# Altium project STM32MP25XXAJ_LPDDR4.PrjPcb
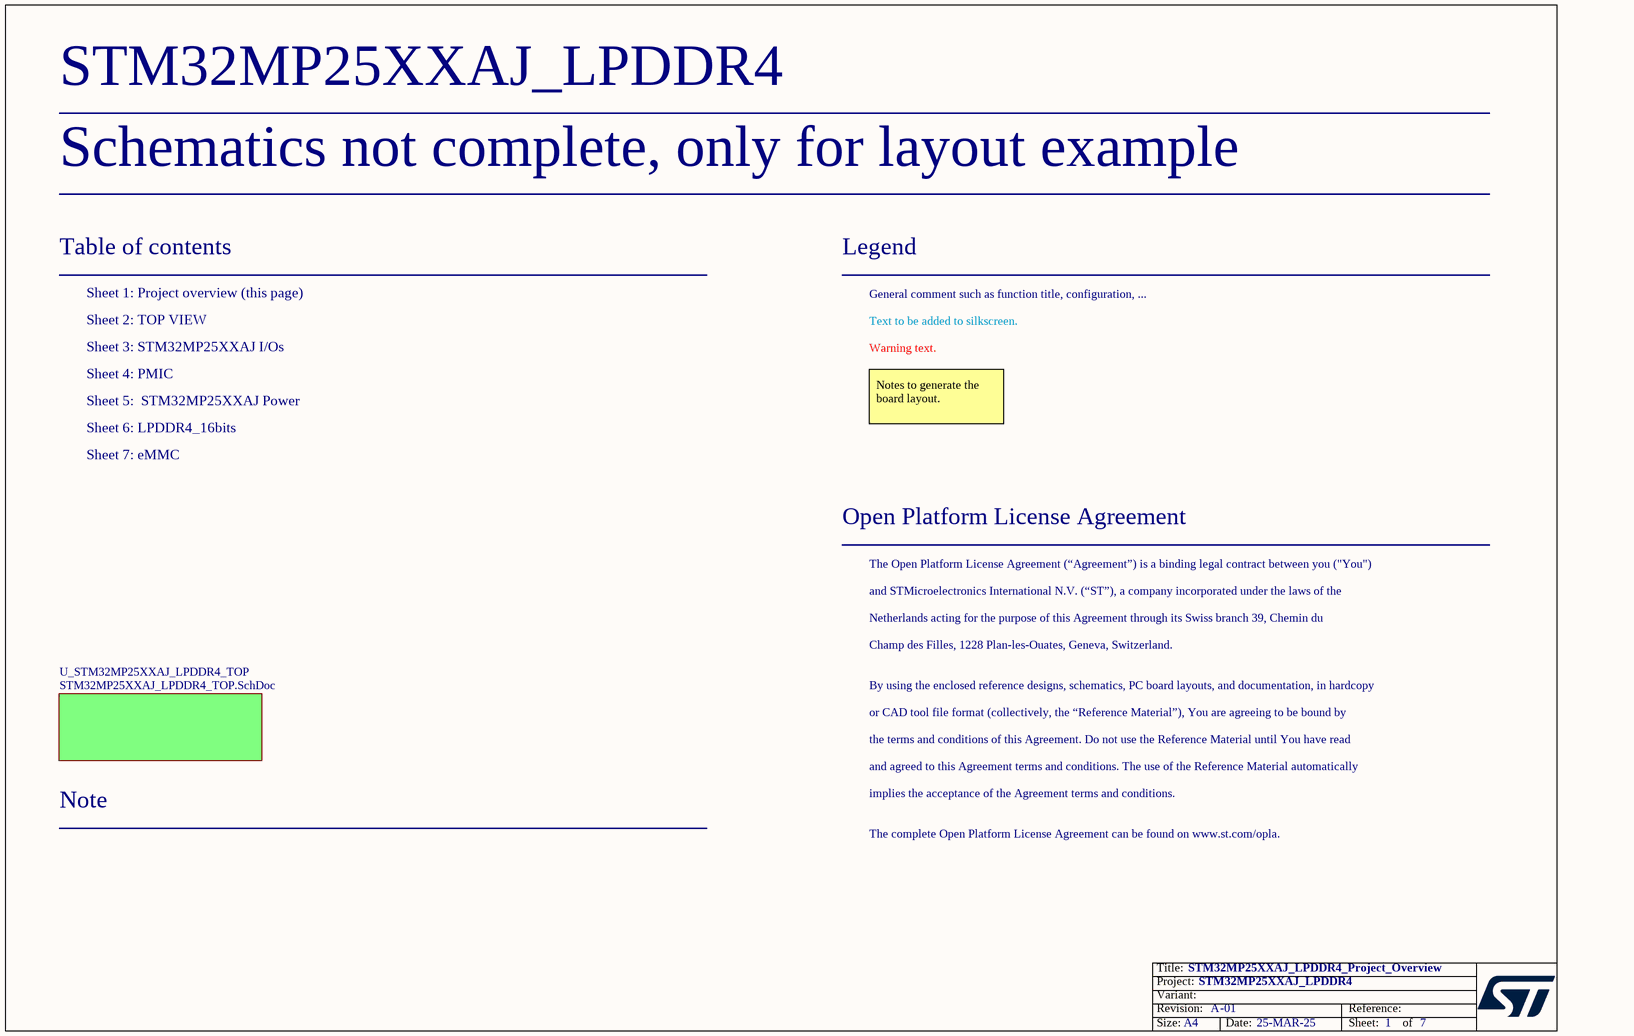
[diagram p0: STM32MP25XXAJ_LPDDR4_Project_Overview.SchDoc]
Board_Assembly_Revision: 01; Board_Document_Date: 25-MAR-25; Board_Name: STM32MP25XXAJ_LPDDR4; Board_PCB_Revision: A
7 sheets, 188 parts. Net scope: flat (ports and power ports of the same name join across sheets).
Board file: STM32MP25XXAJ_LPDDR4.PcbDoc
Sheets:
  STM32MP25XXAJ_LPDDR4_Project_Overview.SchDoc
    U_STM32MP25XXAJ_LPDDR4_TOP = STM32MP25XXAJ_LPDDR4_TOP.SchDoc
      U_STM32MP25XXAJ I_Os = STM32MP25XXAJ I_Os.SchDoc
      U_PMIC = PMIC.SchDoc
      U_STM32MP25XXAJ Power = STM32MP25XXAJ Power.SchDoc
      U_eMMC = eMMC.SchDoc
      U_LPDDR4_16bits = LPDDR4_16bits.SchDoc

## Sheet STM32MP25XXAJ_LPDDR4_Project_Overview.SchDoc: STM32MP25XXAJ_LPDDR4_Project_Overview
size A4; Date: Not used; ApprovedBy: Not used; CheckedBy: Not used; Author: Not used; CompanyName: STMicroelectronics; DrawnBy: Not used; Engineer: Not used; Organization: Not used; Address1: Not used; Address2: Not used; Address3: Not used; Address4: Not used; DocumentNumber: 1; Revision: Not used; SheetNumber: 1; SheetTotal: 7

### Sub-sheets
U_STM32MP25XXAJ_LPDDR4_TOP = STM32MP25XXAJ_LPDDR4_TOP.SchDoc: no entries

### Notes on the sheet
- Schematics not complete, only for layout example
- Table of contents
- Sheet 1: Project overview (this page)
- Legend
- General comment such as function title, configuration, ...
- Sheet 2: TOP VIEW
- Sheet 3: STM32MP25XXAJ I/Os
- Sheet 4: PMIC
- Text to be added to silkscreen.
- Warning text.
- Sheet 5:  STM32MP25XXAJ Power
- Sheet 6: LPDDR4_16bits
- Notes to generate the board layout.
- Sheet 7: eMMC
- Open Platform License Agreement
- The Open Platform License Agreement (“Agreement”) is a binding legal contract between you ("You")
- and STMicroelectronics International N.V. (“ST”), a company incorporated under the laws of the
- Netherlands acting for the purpose of this Agreement through its Swiss branch 39, Chemin du
- Champ des Filles, 1228 Plan-les-Ouates, Geneva, Switzerland.
- By using the enclosed reference designs, schematics, PC board layouts, and documentation, in hardcopy
- or CAD tool file format (collectively, the “Reference Material”), You are agreeing to be bound by
- the terms and conditions of this Agreement. Do not use the Reference Material until You have read
- and agreed to this Agreement terms and conditions. The use of the Reference Material automatically
- Note
- implies the acceptance of the Agreement terms and conditions.
- The complete Open Platform License Agreement can be found on www.st.com/opla.

## Sheet STM32MP25XXAJ_LPDDR4_TOP.SchDoc: TOP
size A4; Date: Not used; ApprovedBy: Not used; CheckedBy: Not used; Author: Not used; CompanyName: STMicroelectronics; DrawnBy: Not used; Engineer: Not used; Organization: Not used; Address1: Not used; Address2: Not used; Address3: Not used; Address4: Not used; DocumentNumber: 2; Revision: Not used; SheetNumber: 2; SheetTotal: 7
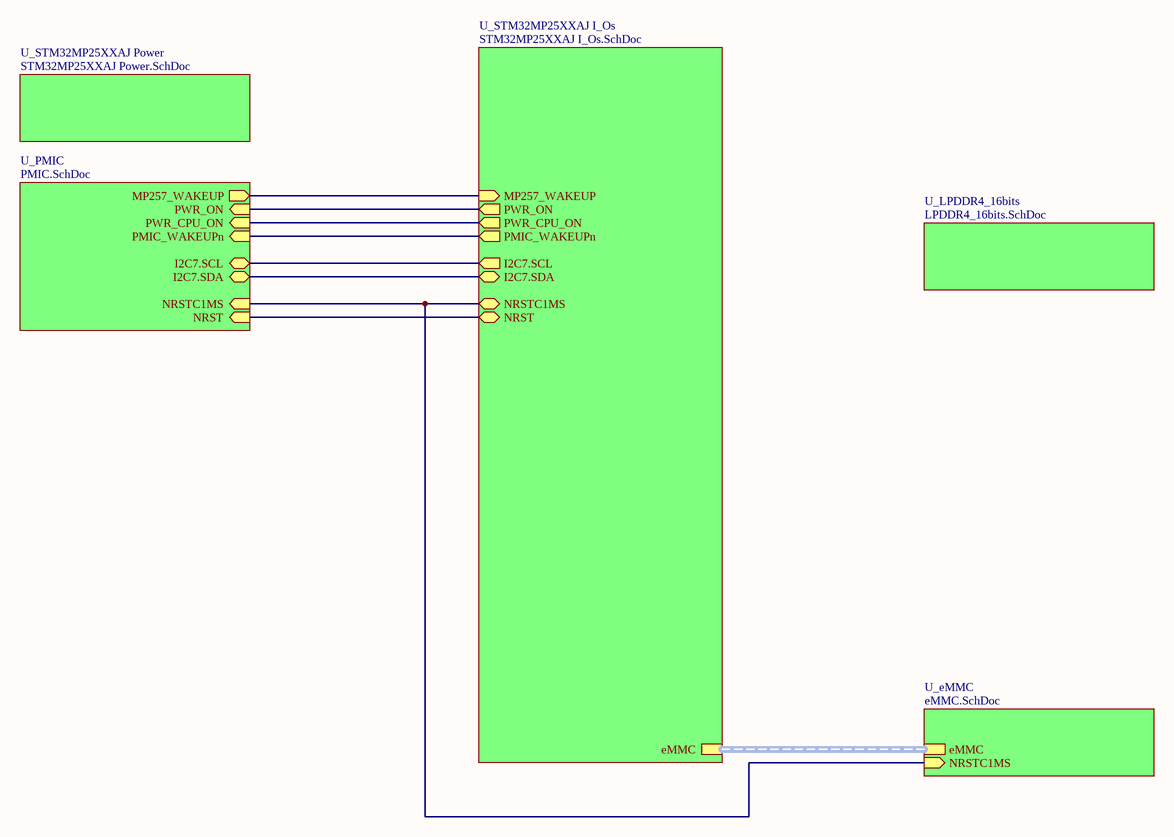
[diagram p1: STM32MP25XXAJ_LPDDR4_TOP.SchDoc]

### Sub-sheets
U_eMMC = eMMC.SchDoc: eMMC (harness eMMC), NRSTC1MS (in)
U_LPDDR4_16bits = LPDDR4_16bits.SchDoc: no entries
U_PMIC = PMIC.SchDoc: PMIC_WAKEUPn (in), NRST (in), I2C7.SCL (bidir), PWR_ON (in), PWR_CPU_ON (in), NRSTC1MS (in), I2C7.SDA (bidir), MP257_WAKEUP (out)
U_STM32MP25XXAJ I_Os = STM32MP25XXAJ I_Os.SchDoc: NRST (bidir), PWR_ON (out), NRSTC1MS (bidir), I2C7.SDA (bidir), I2C7.SCL (out), PWR_CPU_ON (out), MP257_WAKEUP (in), PMIC_WAKEUPn (out), eMMC (harness eMMC)
U_STM32MP25XXAJ Power = STM32MP25XXAJ Power.SchDoc: no entries

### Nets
(unnamed): sheet U_STM32MP25XXAJ I_Os/NRST, sheet U_PMIC/NRST
(unnamed): sheet U_STM32MP25XXAJ I_Os/PWR_ON, sheet U_PMIC/PWR_ON  [a separate net that carries the same name]
(unnamed): sheet U_STM32MP25XXAJ I_Os/NRSTC1MS, sheet U_PMIC/NRSTC1MS, sheet U_eMMC/NRSTC1MS  [a separate net that carries the same name]
(unnamed): sheet U_STM32MP25XXAJ I_Os/I2C7.SDA, sheet U_PMIC/I2C7.SDA  [a separate net that carries the same name]
(unnamed): sheet U_STM32MP25XXAJ I_Os/I2C7.SCL, sheet U_PMIC/I2C7.SCL  [a separate net that carries the same name]
(unnamed): sheet U_STM32MP25XXAJ I_Os/PWR_CPU_ON, sheet U_PMIC/PWR_CPU_ON  [a separate net that carries the same name]
(unnamed): sheet U_STM32MP25XXAJ I_Os/MP257_WAKEUP, sheet U_PMIC/MP257_WAKEUP  [a separate net that carries the same name]
(unnamed): sheet U_STM32MP25XXAJ I_Os/PMIC_WAKEUPn, sheet U_PMIC/PMIC_WAKEUPn  [a separate net that carries the same name]

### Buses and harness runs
harness sheet U_eMMC/eMMC = sheet U_STM32MP25XXAJ I_Os/eMMC

## Sheet STM32MP25XXAJ I_Os.SchDoc: STM32MP25XXAJ  I/Os
size A3; Date: Not used; ApprovedBy: Not used; CheckedBy: Not used; Author: Not used; CompanyName: STMicroelectronics; DrawnBy: Not used; Engineer: Not used; Organization: Not used; Address1: Not used; Address2: Not used; Address3: Not used; Address4: Not used; DocumentNumber: 3; Revision: Not used; SheetNumber: 3; SheetTotal: 7
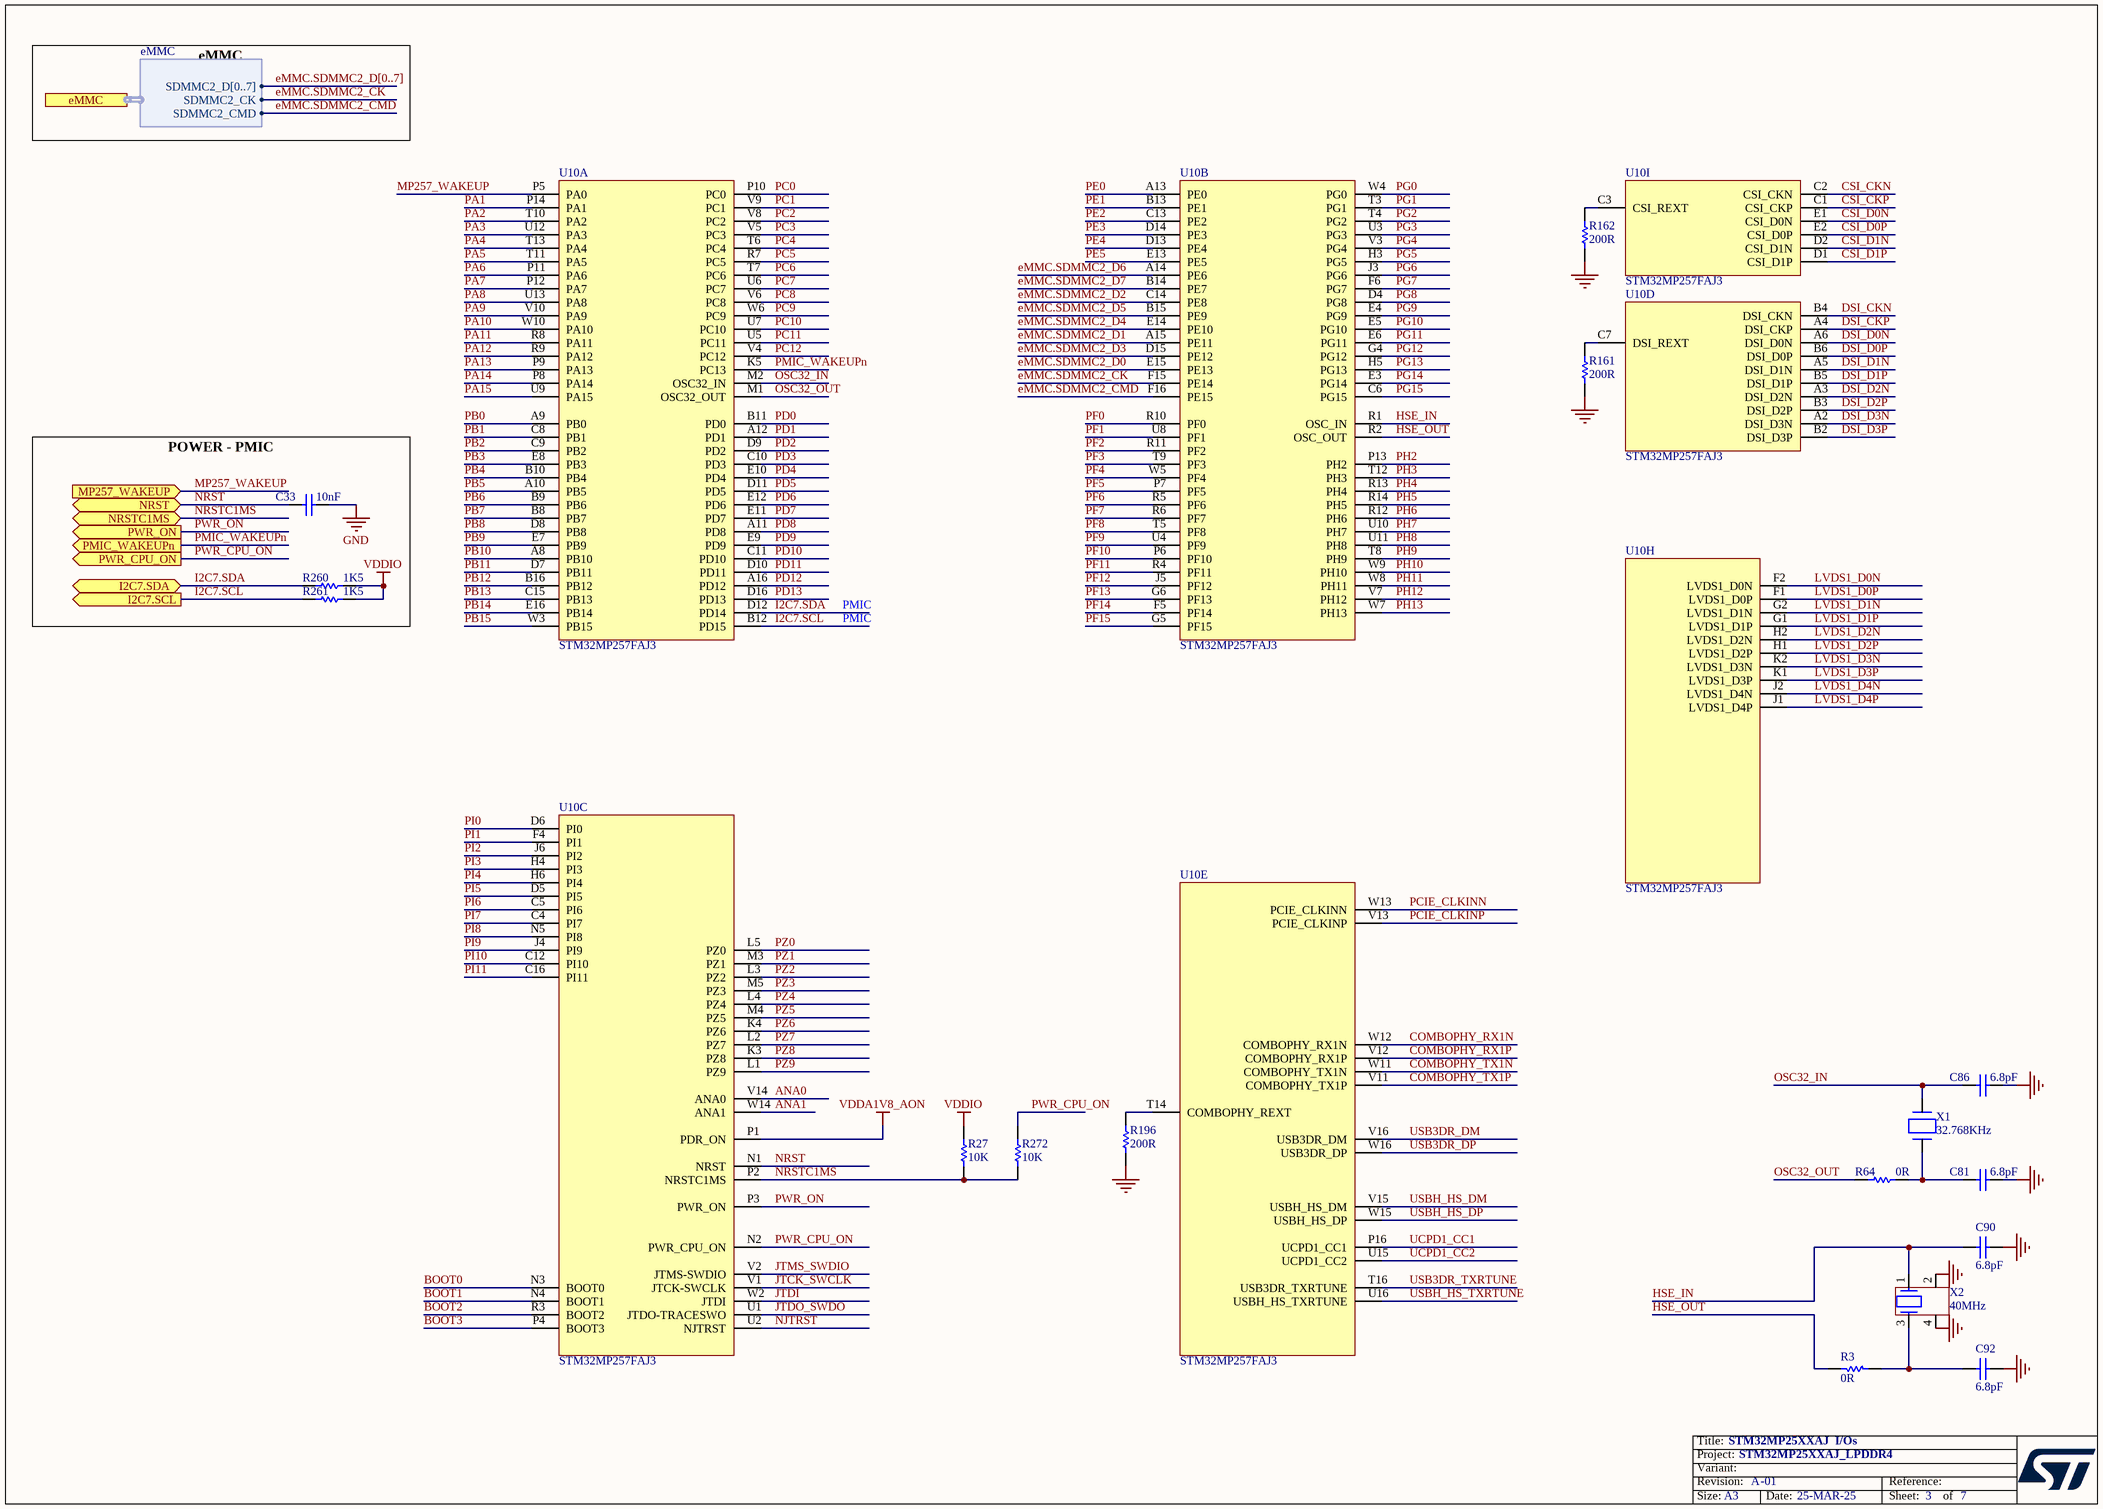
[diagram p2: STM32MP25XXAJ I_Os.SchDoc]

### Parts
C33  value 10nF  [C0402]  (hidden comment: Capacitor)
C81  value 6.8pF  [C0402]  (hidden comment: Capacitor)
C86  value 6.8pF  [C0402]  (hidden comment: Capacitor)
C90  value 6.8pF  [C0402]  (hidden comment: Capacitor)
C92  value 6.8pF  [C0402]  (hidden comment: Capacitor)
R3  value 0R  [R0402]
R27  value 10K  [R0402]  (hidden comment: Resistor)
R64  value 0R  [R0402]
R161  value 200R  [R0402]  (hidden comment: Resistor)
R162  value 200R  [R0402]  (hidden comment: Resistor)
R196  value 200R  [R0402]  (hidden comment: Resistor)
R260  value 1K5  [R0402]  (hidden comment: Resistor)
R261  value 1K5  [R0402]  (hidden comment: Resistor)
R272  value 10K  [R0402]  (hidden comment: Resistor)
U10  value STM32MP257FAJ3  [ICC_TFBGA361_16X16_P080]  (hidden comment: IC_STM32MP257FAJ3)  (parts A,B,C,D,E,H,I of 9)
X1  value 32.768KHz  [CRY_NX2012SA_2P]  (hidden comment: XTAL_2_PINS)
X2  value 40MHz  [CRY_NX1612SA_4P]  (hidden comment: XTAL_4_PINS)

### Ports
eMMC (harness eMMC), I2C7.SCL (out), I2C7.SDA (bidir), MP257_WAKEUP (in), NRST (bidir), NRSTC1MS (bidir), PMIC_WAKEUPn (out), PWR_CPU_ON (out), PWR_ON (out)

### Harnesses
eMMC: SDMMC2_CK, SDMMC2_CMD, SDMMC2_D[0..7]

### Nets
GND: C33.1 C81.2 C86.2 C90.1 C92.2 R161.2 R162.2 R196.1 X2.2 X2.4
VDDA1V8_AON: U10.P1(PDR_ON)
VDDIO: R27.2 R260.2 R261.2
ANA0: U10.V14(ANA0)
ANA1: U10.W14(ANA1)
BOOT0: U10.N3(BOOT0)
BOOT1: U10.N4(BOOT1)
BOOT2: U10.R3(BOOT2)
BOOT3: U10.P4(BOOT3)
COMBOPHY_RX1N: U10.W12(COMBOPHY_RX1N)
COMBOPHY_RX1P: U10.V12(COMBOPHY_RX1P)
COMBOPHY_TX1N: U10.W11(COMBOPHY_TX1N)
COMBOPHY_TX1P: U10.V11(COMBOPHY_TX1P)
CSI_CKN: U10.C2(CSI_CKN)
CSI_CKP: U10.C1(CSI_CKP)
CSI_D0N: U10.E1(CSI_D0N)
CSI_D0P: U10.E2(CSI_D0P)
CSI_D1N: U10.D2(CSI_D1N)
CSI_D1P: U10.D1(CSI_D1P)
DSI_CKN: U10.B4(DSI_CKN)
DSI_CKP: U10.A4(DSI_CKP)
DSI_D0N: U10.A6(DSI_D0N)
DSI_D0P: U10.B6(DSI_D0P)
DSI_D1N: U10.A5(DSI_D1N)
DSI_D1P: U10.B5(DSI_D1P)
DSI_D2N: U10.A3(DSI_D2N)
DSI_D2P: U10.B3(DSI_D2P)
DSI_D3N: U10.A2(DSI_D3N)
DSI_D3P: U10.B2(DSI_D3P)
eMMC.SDMMC2_CK: U10.F15(PE14) ; port eMMC.SDMMC2_CK
eMMC.SDMMC2_CMD: U10.F16(PE15) ; port eMMC.SDMMC2_CMD
eMMC.SDMMC2_D0: U10.E15(PE13)
eMMC.SDMMC2_D1: U10.A15(PE11)
eMMC.SDMMC2_D2: U10.C14(PE8)
eMMC.SDMMC2_D3: U10.D15(PE12)
eMMC.SDMMC2_D4: U10.E14(PE10)
eMMC.SDMMC2_D5: U10.B15(PE9)
eMMC.SDMMC2_D6: U10.A14(PE6)
eMMC.SDMMC2_D7: U10.B14(PE7)
HSE_IN: C90.2 U10.R1(OSC_IN) X2.1
HSE_OUT: R3.2 U10.R2(OSC_OUT)
I2C7.SCL: R261.1 U10.B12(PD15) ; port I2C7.SCL
I2C7.SDA: R260.1 U10.D12(PD14) ; port I2C7.SDA
JTCK_SWCLK: U10.V1(JTCK-SWCLK)
JTDI: U10.W2(JTDI)
JTDO_SWDO: U10.U1(JTDO-TRACESWO)
JTMS_SWDIO: U10.V2(JTMS-SWDIO)
LVDS1_D0N: U10.F2(LVDS1_D0N)
LVDS1_D0P: U10.F1(LVDS1_D0P)
LVDS1_D1N: U10.G2(LVDS1_D1N)
LVDS1_D1P: U10.G1(LVDS1_D1P)
LVDS1_D2N: U10.H2(LVDS1_D2N)
LVDS1_D2P: U10.H1(LVDS1_D2P)
LVDS1_D3N: U10.K2(LVDS1_D3N)
LVDS1_D3P: U10.K1(LVDS1_D3P)
LVDS1_D4N: U10.J2(LVDS1_D4N)
LVDS1_D4P: U10.J1(LVDS1_D4P)
MP257_WAKEUP: U10.P5(PA0) ; port MP257_WAKEUP
NJTRST: U10.U2(NJTRST)
NRST: C33.2 U10.N1(NRST) ; port NRST
NRSTC1MS: R27.1 R272.1 U10.P2(NRSTC1MS) ; port NRSTC1MS
OSC32_IN: C86.1 U10.M2(OSC32_IN) X1.2(X2)
OSC32_OUT: R64.1 U10.M1(OSC32_OUT)
PA1: U10.P14(PA1)
PA2: U10.T10(PA2)
PA3: U10.U12(PA3)
PA4: U10.T13(PA4)
PA5: U10.T11(PA5)
PA6: U10.P11(PA6)
PA7: U10.P12(PA7)
PA8: U10.U13(PA8)
PA9: U10.V10(PA9)
PA10: U10.W10(PA10)
PA11: U10.R8(PA11)
PA12: U10.R9(PA12)
PA13: U10.P9(PA13)
PA14: U10.P8(PA14)
PA15: U10.U9(PA15)
PB0: U10.A9(PB0)
PB1: U10.C8(PB1)
PB2: U10.C9(PB2)
PB3: U10.E8(PB3)
PB4: U10.B10(PB4)
PB5: U10.A10(PB5)
PB6: U10.B9(PB6)
PB7: U10.B8(PB7)
PB8: U10.D8(PB8)
PB9: U10.E7(PB9)
PB10: U10.A8(PB10)
PB11: U10.D7(PB11)
PB12: U10.B16(PB12)
PB13: U10.C15(PB13)
PB14: U10.E16(PB14)
PB15: U10.W3(PB15)
PC0: U10.P10(PC0)
PC1: U10.V9(PC1)
PC2: U10.V8(PC2)
PC3: U10.V5(PC3)
PC4: U10.T6(PC4)
PC5: U10.R7(PC5)
PC6: U10.T7(PC6)
PC7: U10.U6(PC7)
PC8: U10.V6(PC8)
PC9: U10.W6(PC9)
PC10: U10.U7(PC10)
PC11: U10.U5(PC11)
PC12: U10.V4(PC12)
PCIE_CLKINN: U10.W13(PCIE_CLKINN)
PCIE_CLKINP: U10.V13(PCIE_CLKINP)
PD0: U10.B11(PD0)
PD1: U10.A12(PD1)
PD2: U10.D9(PD2)
PD3: U10.C10(PD3)
PD4: U10.E10(PD4)
PD5: U10.D11(PD5)
PD6: U10.E12(PD6)
PD7: U10.E11(PD7)
PD8: U10.A11(PD8)
PD9: U10.E9(PD9)
PD10: U10.C11(PD10)
PD11: U10.D10(PD11)
PD12: U10.A16(PD12)
PD13: U10.D16(PD13)
PE0: U10.A13(PE0)
PE1: U10.B13(PE1)
PE2: U10.C13(PE2)
PE3: U10.D14(PE3)
PE4: U10.D13(PE4)
PE5: U10.E13(PE5)
PF0: U10.R10(PF0)
PF1: U10.U8(PF1)
PF2: U10.R11(PF2)
PF3: U10.T9(PF3)
PF4: U10.W5(PF4)
PF5: U10.P7(PF5)
PF6: U10.R5(PF6)
PF7: U10.R6(PF7)
PF8: U10.T5(PF8)
PF9: U10.U4(PF9)
PF10: U10.P6(PF10)
PF11: U10.R4(PF11)
PF12: U10.J5(PF12)
PF13: U10.G6(PF13)
PF14: U10.F5(PF14)
PF15: U10.G5(PF15)
PG0: U10.W4(PG0)
PG1: U10.T3(PG1)
PG2: U10.T4(PG2)
PG3: U10.U3(PG3)
PG4: U10.V3(PG4)
PG5: U10.H3(PG5)
PG6: U10.J3(PG6)
PG7: U10.F6(PG7)
PG8: U10.D4(PG8)
PG9: U10.E4(PG9)
PG10: U10.E5(PG10)
PG11: U10.E6(PG11)
PG12: U10.G4(PG12)
PG13: U10.H5(PG13)
PG14: U10.E3(PG14)
PG15: U10.C6(PG15)
PH2: U10.P13(PH2)
PH3: U10.T12(PH3)
PH4: U10.R13(PH4)
PH5: U10.R14(PH5)
PH6: U10.R12(PH6)
PH7: U10.U10(PH7)
PH8: U10.U11(PH8)
PH9: U10.T8(PH9)
PH10: U10.W9(PH10)
PH11: U10.W8(PH11)
PH12: U10.V7(PH12)
PH13: U10.W7(PH13)
PI0: U10.D6(PI0)
PI1: U10.F4(PI1)
PI2: U10.J6(PI2)
PI3: U10.H4(PI3)
PI4: U10.H6(PI4)
PI5: U10.D5(PI5)
PI6: U10.C5(PI6)
PI7: U10.C4(PI7)
PI8: U10.N5(PI8)
PI9: U10.J4(PI9)
PI10: U10.C12(PI10)
PI11: U10.C16(PI11)
PMIC_WAKEUPn: U10.K5(PC13) ; port PMIC_WAKEUPn
PWR_CPU_ON: R272.2 U10.N2(PWR_CPU_ON) ; port PWR_CPU_ON
PWR_ON: U10.P3(PWR_ON) ; port PWR_ON
PZ0: U10.L5(PZ0)
PZ1: U10.M3(PZ1)
PZ2: U10.L3(PZ2)
PZ3: U10.M5(PZ3)
PZ4: U10.L4(PZ4)
PZ5: U10.M4(PZ5)
PZ6: U10.K4(PZ6)
PZ7: U10.L2(PZ7)
PZ8: U10.K3(PZ8)
PZ9: U10.L1(PZ9)
UCPD1_CC1: U10.P16(UCPD1_CC1)
UCPD1_CC2: U10.U15(UCPD1_CC2)
USB3DR_DM: U10.V16(USB3DR_DM)
USB3DR_DP: U10.W16(USB3DR_DP)
USB3DR_TXRTUNE: U10.T16(USB3DR_TXRTUNE)
USBH_HS_DM: U10.V15(USBH_HS_DM)
USBH_HS_DP: U10.W15(USBH_HS_DP)
USBH_HS_TXRTUNE: U10.U16(USBH_HS_TXRTUNE)
NetC81_1: C81.1 R64.2 X1.1(X1)
NetC92_1: C92.1 R3.1 X2.3
NetR161_1: R161.1 U10.C7(DSI_REXT)
NetR162_1: R162.1 U10.C3(CSI_REXT)
NetR196_2: R196.2 U10.T14(COMBOPHY_REXT)

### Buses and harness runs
bus eMMC.SDMMC2_D[0..7]

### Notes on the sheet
- eMMC
- POWER - PMIC
- PMIC

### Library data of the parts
C33 = MCD-00011: Capacitor, MLCC, 10nF, 16V, X7R, 10%, 0402, T=0.5mm; Manufacturer_Part_Number: CC0402KRX7R7BB103; Manufacturer: YAGEO; Provided_By: SUBCO; Initial_Board_Reference: MB1274
C81 C86 = MCD-00674: Capacitor, MLCC, 6.8pF, 50V, NPO, +-0.25pF, 0402, T=0.5mm; Manufacturer_Part_Number: CC0402CRNPO9BN6R8; Manufacturer: YAGEO; Part_Preference: Recommended; Provided_By: SUBCO; Initial_Board_Reference: MB1319; Path: ws/MCD_ApplicationBoards/Lists/MCDPARTSdatabase; Item Type: Item; Component_Country_Of_Origin: China; ID: 3068; ShowFields: YES
C90 C92 = MCD-00674: Capacitor, MLCC, 6.8pF, 50V, NPO, +-0.25pF, 0402, T=0.5mm; Manufacturer_Part_Number: CC0402CRNPO9BN6R8; Manufacturer: YAGEO; Part_Preference: Recommended; Provided_By: SUBCO; Initial_Board_Reference: MB1319; Component_Country_Of_Origin: China; ID: 3068; ShowFields: YES
R3 R64 = MCD-00052: Resistor,0R,0402,5%,1/16W; Manufacturer_Part_Number: RC0402JR-070RL; Manufacturer: YAGEO; Part_Preference: Recommended; Provided_By: SUBCO; Initial_Board_Reference: mb1274; Order_Code_RS: 618-5804; Component_Country_Of_Origin: China; ID: 2540; ShowFields: YES
R27 R272 = MCD-00053: Resistor,10K,0402,1%,1/16W; BMS_Part_Number: 9131590; Part_Preference: Recommended; Manufacturer: YAGEO; Manufacturer_Part_Number: RC0402FR-0710KL; Component_Country_Of_Origin: China; ID: 2539; ShowFields: YES
R161 R162 = MCD-00417: Resistor,200R,0402,1%,1/16W; Manufacturer_Part_Number: RC0402FR-07200RL; Manufacturer: YAGEO; Part_Preference: Recommended; ECCN_US: EAR99; ECCN_EU: NEC; Provided_By: SUBCO
R196 = MCD-00417: Resistor,200R,0402,1%,1/16W; Part_Preference: Recommended; Manufacturer: YAGEO; Manufacturer_Part_Number: RC0402FR-07200RL
R260 R261 = MCD-00068: Resistor,1K5,0402,1%,1/16W; Part_Preference: Recommended; Manufacturer: YAGEO; Manufacturer_Part_Number: RC0402FR-071K5L; Component_Country_Of_Origin: China; ID: 2524; ShowFields: YES
U10 = MCD-04441: MPU, Dual Core ARM cortex-A35 64-bit + M33 32-bit,  808KB SRAM, With Crypto; Part_Type: IC; Part_Preference: Recommended; Manufacturer: STMICROELECTRONICS; ShowFields: YES; ID: 6557
X1 = MCD-01479: Crystal, 32.768kHz, 6pF, +/-20ppm, 80K, 2.05x1.2mm; BMS_Part_Number: 9157049; Part_Type: Crystal_Osc; Part_Preference: Recommended; Manufacturer: NDK; Manufacturer_Part_Number: NX2012SA-32.768KHZ-EXS00A-MU00527; Component_Country_Of_Origin: Unknown; ShowFields: YES; ID: 3579
X2 = MCD-02344: Crystal, 40MHz, 6pF, +/-20ppm, 80R, 1.6x1.2mm; Part_Type: Crystal_Osc; Part_Preference: Recommended; Manufacturer: NDK; Manufacturer_Part_Number: NX1612SA-40MHZ-EXS00A-CS13836; Component_Country_Of_Origin: Unknown; ShowFields: YES; ID: 4450

## Sheet PMIC.SchDoc: PMIC
size A3; Date: Not used; ApprovedBy: Not used; CheckedBy: Not used; Author: Not used; CompanyName: STMicroelectronics; DrawnBy: Not used; Engineer: Not used; Organization: Not used; Address1: Not used; Address2: Not used; Address3: Not used; Address4: Not used; DocumentNumber: 4; Revision: Not used; SheetNumber: 4; SheetTotal: 7
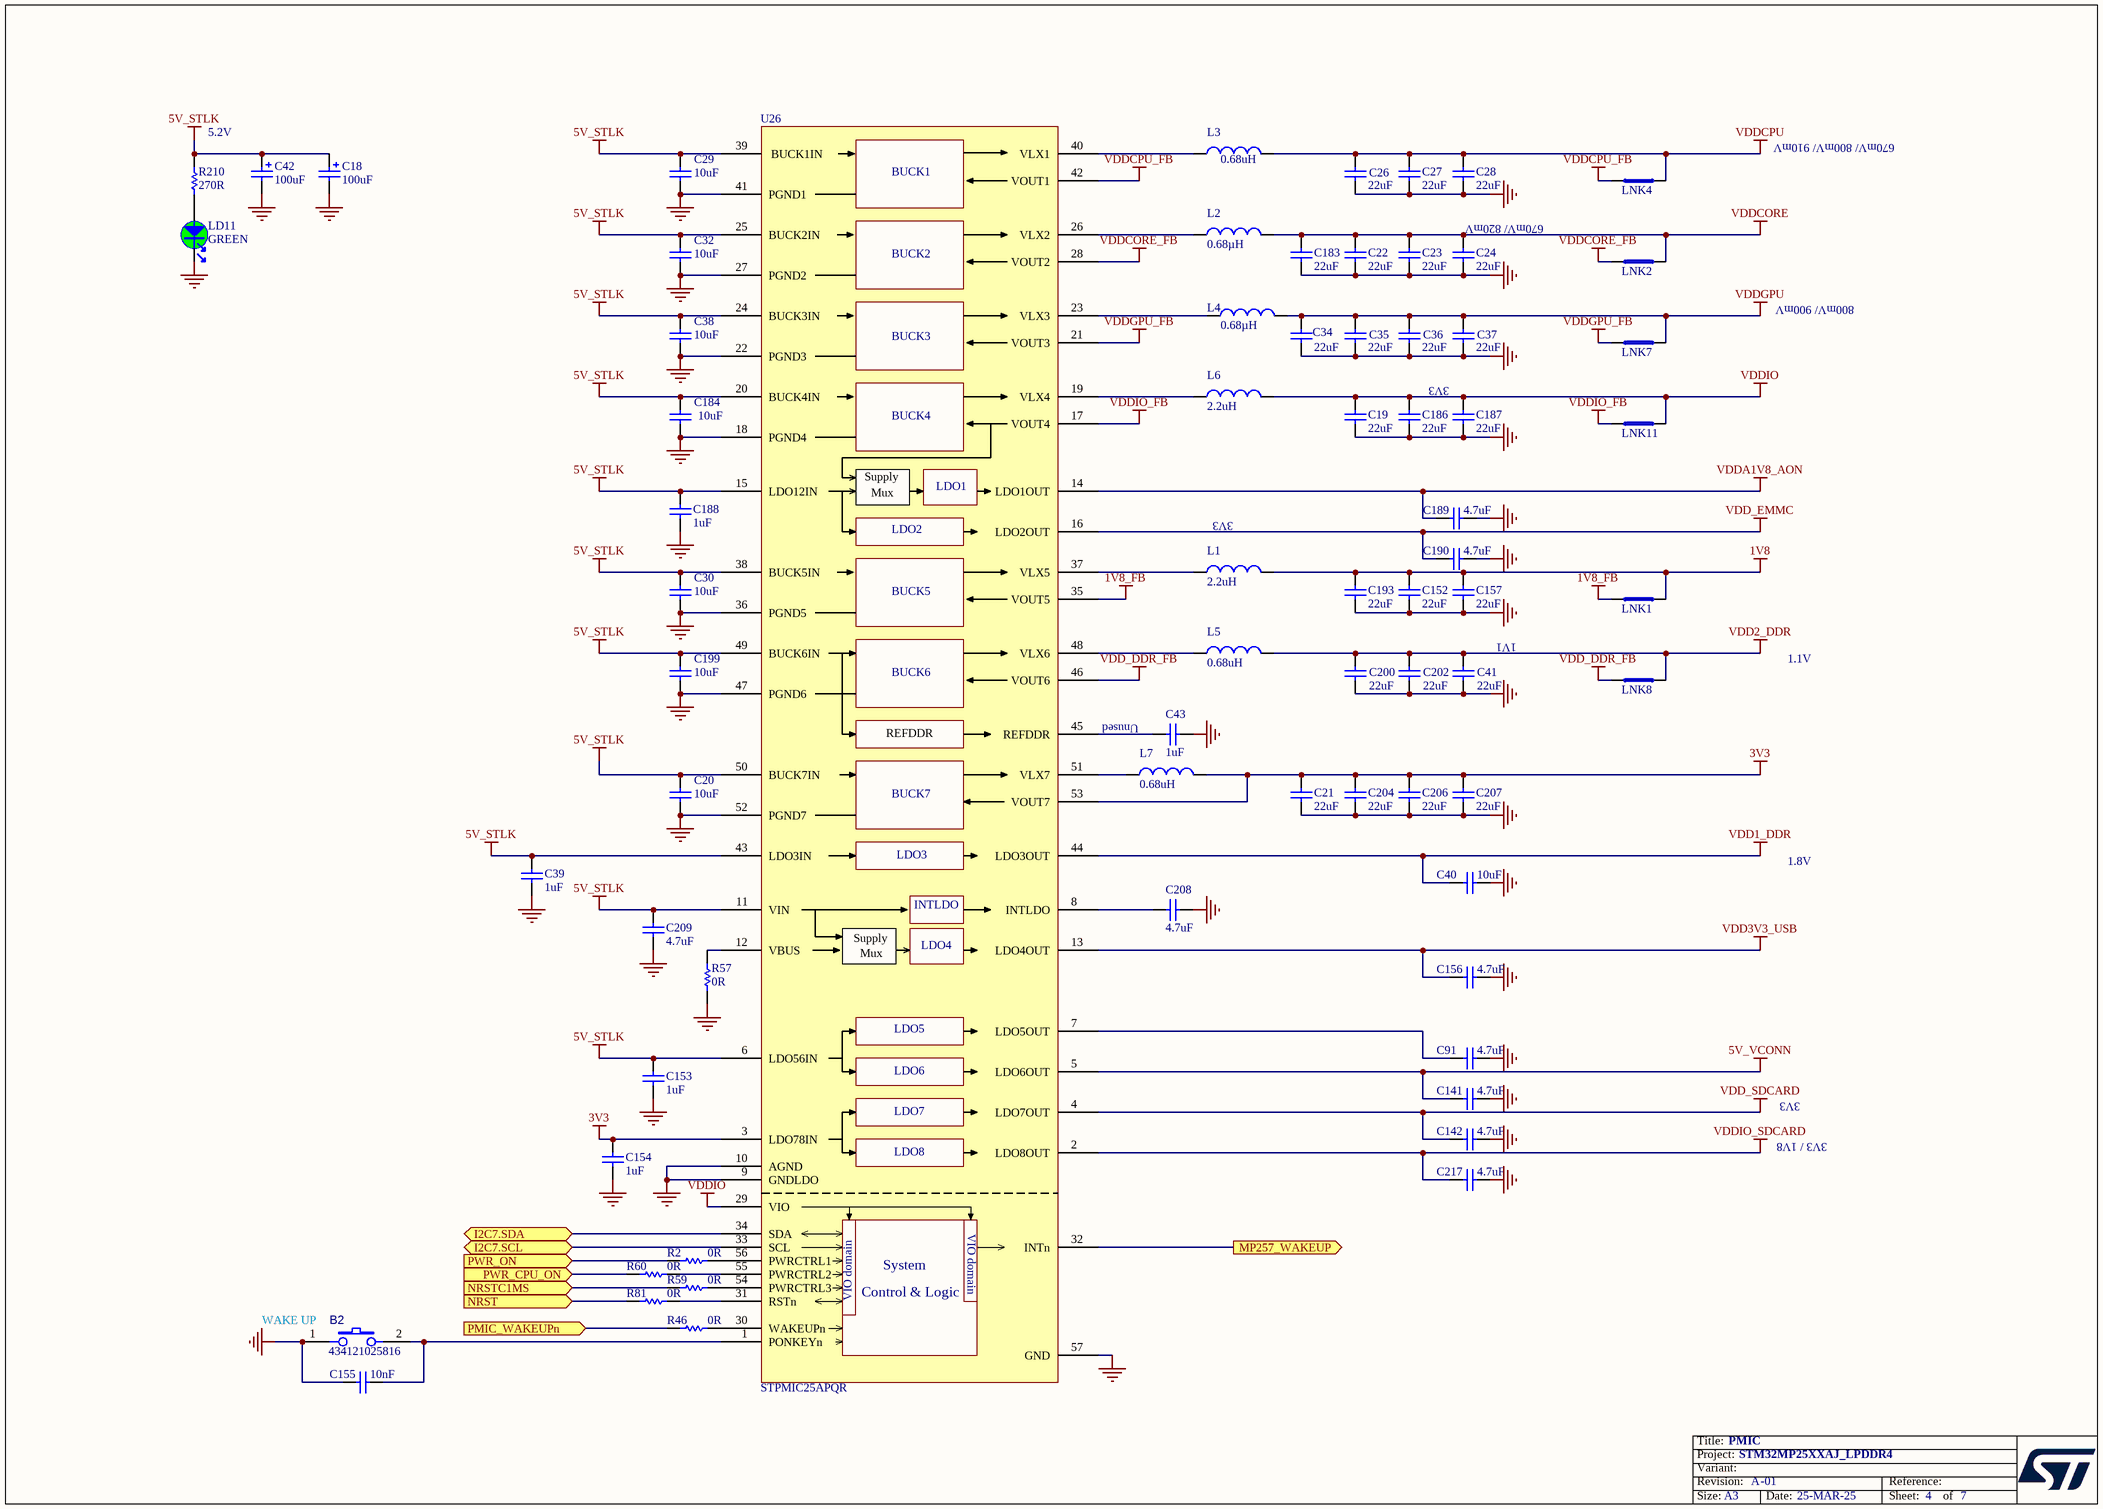
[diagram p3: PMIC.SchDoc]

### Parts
B2  value 434121025816  [SWI_WE_434121025816]  (hidden comment: SW_PUSH_SMD_2P)
C18  value 100uF  [CPOL_TCJ-B_1210_H210]  (hidden comment: Cap_POL_TANA)
C19  value 22uF  [C0805]  (hidden comment: Capacitor)
C20  value 10uF  [C0603]  (hidden comment: Capacitor)
C21  value 22uF  [C0805]  (hidden comment: Capacitor)
C22  value 22uF  [C0603]  (hidden comment: Capacitor)
C23  value 22uF  [C0603]  (hidden comment: Capacitor)
C24  value 22uF  [C0603]  (hidden comment: Capacitor)
C26  value 22uF  [C0603]  (hidden comment: Capacitor)
C27  value 22uF  [C0603]  (hidden comment: Capacitor)
C28  value 22uF  [C0603]  (hidden comment: Capacitor)
C29  value 10uF  [C0603]  (hidden comment: Capacitor)
C30  value 10uF  [C0603]  (hidden comment: Capacitor)
C32  value 10uF  [C0603]  (hidden comment: Capacitor)
C34  value 22uF  [C0603]  (hidden comment: Capacitor)
C35  value 22uF  [C0603]  (hidden comment: Capacitor)
C36  value 22uF  [C0603]  (hidden comment: Capacitor)
C37  value 22uF  [C0603]  (hidden comment: Capacitor)
C38  value 10uF  [C0603]  (hidden comment: Capacitor)
C39  value 1uF  [C0402]  (hidden comment: Capacitor)
C40  value 10uF  [C0402]  (hidden comment: Capacitor)
C41  value 22uF  [C0603]  (hidden comment: Capacitor)
C42  value 100uF  [CPOL_TCJ-B_1210_H210]  (hidden comment: Cap_POL_TANA)
C43  value 1uF  [C0402]  (hidden comment: Capacitor)
C91  value 4.7uF  [C0402]  (hidden comment: Capacitor)
C141  value 4.7uF  [C0402]  (hidden comment: Capacitor)
C142  value 4.7uF  [C0402]  (hidden comment: Capacitor)
C152  value 22uF  [C0805]  (hidden comment: Capacitor)
C153  value 1uF  [C0402]  (hidden comment: Capacitor)
C154  value 1uF  [C0402]  (hidden comment: Capacitor)
C155  value 10nF  [C0402]  (hidden comment: Capacitor)
C156  value 4.7uF  [C0402]  (hidden comment: Capacitor)
C157  value 22uF  [C0805]  (hidden comment: Capacitor)
C183  value 22uF  [C0603]  (hidden comment: Capacitor)
C184  value 10uF  [C0603]  (hidden comment: Capacitor)
C186  value 22uF  [C0805]  (hidden comment: Capacitor)
C187  value 22uF  [C0805]  (hidden comment: Capacitor)
C188  value 1uF  [C0402]  (hidden comment: Capacitor)
C189  value 4.7uF  [C0402]  (hidden comment: Capacitor)
C190  value 4.7uF  [C0402]  (hidden comment: Capacitor)
C193  value 22uF  [C0805]  (hidden comment: Capacitor)
C199  value 10uF  [C0603]  (hidden comment: Capacitor)
C200  value 22uF  [C0603]  (hidden comment: Capacitor)
C202  value 22uF  [C0603]  (hidden comment: Capacitor)
C204  value 22uF  [C0805]  (hidden comment: Capacitor)
C206  value 22uF  [C0805]  (hidden comment: Capacitor)
C207  value 22uF  [C0805]  (hidden comment: Capacitor)
C208  value 4.7uF  [C0402]  (hidden comment: Capacitor)
C209  value 4.7uF  [C0402]  (hidden comment: Capacitor)
C217  value 4.7uF  [C0402]  (hidden comment: Capacitor)
L1  value 2.2uH  [IND_2016_MURATA_LQM2MPN2R2NG0]  (hidden comment: Inductor)
L2  value 0.68µH  [IND_2520_TOKO_DFE252012P]  (hidden comment: Inductor)
L3  value 0.68uH  [IND_2016_MURATA_LQM2MPN2R2NG0]  (hidden comment: Inductor)
L4  value 0.68µH  [IND_2520_TOKO_DFE252012P]  (hidden comment: Inductor)
L5  value 0.68uH  [IND_2016_MURATA_LQM2MPN2R2NG0]  (hidden comment: Inductor)
L6  value 2.2uH  [IND_2016_MURATA_LQM2MPN2R2NG0]  (hidden comment: Inductor)
L7  value 0.68uH  [IND_2016_MURATA_LQM2MPN2R2NG0]  (hidden comment: Inductor)
LD11  value GREEN  [LED_0603_OSRAM_LG-Q396-PS-35_GREEN_1A2K_H0P4]  (hidden comment: LED_green)
LNK1  link_200  [LINK200]  (value not drawn)  (no BOM)
LNK2  link_200  [LINK200]  (value not drawn)  (no BOM)
LNK4  link_200  [LINK200]  (value not drawn)  (no BOM)
LNK7  link_200  [LINK200]  (value not drawn)  (no BOM)
LNK8  link_200  [LINK200]  (value not drawn)  (no BOM)
LNK11  link_200  [LINK200]  (value not drawn)  (no BOM)
R2  value 0R  [R0402]
R46  value 0R  [R0402]
R57  value 0R  [R0402]
R59  value 0R  [R0402]
R60  value 0R  [R0402]
R81  value 0R  [R0402]
R210  value 270R  [R0402]  (hidden comment: Resistor)
U26  STPMIC25APQR  [ICC_QFN56-EPAD_6P5X6P5_P040]

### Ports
I2C7.SCL (bidir), I2C7.SDA (bidir), MP257_WAKEUP (out), NRST (in), NRSTC1MS (in), PMIC_WAKEUPn (in), PWR_CPU_ON (in), PWR_ON (in)

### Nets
1V8: C152.2 C157.2 C193.2 L1.2 LNK1.2
1V8_FB: LNK1.1 U26.35(VOUT5)
3V3: C21.2 C154.2 C204.2 C206.2 C207.2 L7.2 U26.3(LDO78IN) U26.53(VOUT7)
5V_STLK: C18.1 C20.2 C29.2 C30.2 C32.2 C38.2 C39.2 C42.1 C153.2 C184.2 C188.2 C199.2 C209.2 R210.1 U26.6(LDO56IN) U26.11(VIN) U26.15(LDO12IN) U26.20(BUCK4IN) U26.24(BUCK3IN) U26.25(BUCK2IN) U26.38(BUCK5IN) U26.39(BUCK1IN) U26.43(LDO3IN) U26.49(BUCK6IN) U26.50(BUCK7IN)
5V_VCONN: C141.1 U26.5(LDO6OUT)
GND: B2.1 C18.2 C19.1 C20.1 C21.1 C22.1 C23.1 C24.1 C26.1 C27.1 C28.1 C29.1 C30.1 C32.1 C34.1 C35.1 C36.1 C37.1 C38.1 C39.1 C40.1 C41.1 C42.2 C43.1 C91.2 C141.2 C142.2 C152.1 C153.1 C154.1 C155.1 C156.1 C157.1 C183.1 C184.1 C186.1 C187.1 C188.1 C189.1 C190.2 C193.1 C199.1 C200.1 C202.1 C204.1 C206.1 C207.1 C208.2 C209.1 C217.2 LD11.2 R57.1 U26.9(GNDLDO) U26.10(AGND) U26.18(PGND4) U26.22(PGND3) U26.27(PGND2) U26.36(PGND5) U26.41(PGND1) U26.47(PGND6) U26.52(PGND7) U26.57(GND)
VDD1_DDR: C40.2 U26.44(LDO3OUT)
VDD2_DDR: C41.2 C200.2 C202.2 L5.2 LNK8.2
VDD3V3_USB: C156.2 U26.13(LDO4OUT)
VDD_DDR_FB: LNK8.1 U26.46(VOUT6)
VDD_EMMC: C190.1 U26.16(LDO2OUT)
VDD_SDCARD: C142.1 U26.4(LDO7OUT)
VDDA1V8_AON: C189.2 U26.14(LDO1OUT)
VDDCORE: C22.2 C23.2 C24.2 C183.2 L2.2 LNK2.2
VDDCORE_FB: LNK2.1 U26.28(VOUT2)
VDDCPU: C26.2 C27.2 C28.2 L3.2 LNK4.1
VDDCPU_FB: LNK4.2 U26.42(VOUT1)
VDDGPU: C34.2 C35.2 C36.2 C37.2 L4.2 LNK7.2
VDDGPU_FB: LNK7.1 U26.21(VOUT3)
VDDIO: C19.2 C186.2 C187.2 L6.2 LNK11.2 U26.29(VIO)
VDDIO_FB: LNK11.1 U26.17(VOUT4)
VDDIO_SDCARD: C217.1 U26.2(LDO8OUT)
I2C7.SCL: U26.33(SCL) ; port I2C7.SCL
I2C7.SDA: U26.34(SDA) ; port I2C7.SDA
MP257_WAKEUP: U26.32(INTn) ; port MP257_WAKEUP
NRST: R81.1 ; port NRST
NRSTC1MS: R59.1 ; port NRSTC1MS
PMIC_WAKEUPn: R46.1 ; port PMIC_WAKEUPn
PWR_CPU_ON: R60.1 ; port PWR_CPU_ON
PWR_ON: R2.1 ; port PWR_ON
NetB2_2: B2.2 C155.2 U26.1(PONKEYn)
NetC43_2: C43.2 U26.45(REFDDR)
NetC91_1: C91.1 U26.7(LDO5OUT)
NetC208_1: C208.1 U26.8(INTLDO)
NetL1_1: L1.1 U26.37(VLX5)
NetL2_1: L2.1 U26.26(VLX2)
NetL3_1: L3.1 U26.40(VLX1)
NetL4_1: L4.1 U26.23(VLX3)
NetL5_1: L5.1 U26.48(VLX6)
NetL6_1: L6.1 U26.19(VLX4)
NetL7_1: L7.1 U26.51(VLX7)
NetLD11_1: LD11.1 R210.2
NetR2_2: R2.2 U26.56(PWRCTRL1)
NetR46_2: R46.2 U26.30(WAKEUPn)
NetR57_2: R57.2 U26.12(VBUS)
NetR59_2: R59.2 U26.54(PWRCTRL3)
NetR60_2: R60.2 U26.55(PWRCTRL2)
NetR81_2: R81.2 U26.31(RSTn)

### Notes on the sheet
- 5.2V
- 670mV/ 800mV/ 910mV
- (near C24) 670mV/ 820mV
- 800mV/ 900mV
- 3V3
- (near L1) 3V3
- 1V1
- Unused
- 1.1V
- 1.8V
- 3V3 / 1V8
- (near B2) WAKE UP

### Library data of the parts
B2 = MCD-03492: Switch tactile, SPST-NO, 50mA, 12V, 6x3.8mm; Part_Type: Misc; Part_Preference: Recommended; Manufacturer: WURTH ELEKTRONIC; Component_Country_Of_Origin: China°; ShowFields: YES; ID: 5608
C18 C42 = MCD-01796: Capacitor, Tantalum, 100uF, 6V3, 40mR, +/-20%,  Type_B (3528 metric), T=1.9mm; Part_Preference: Recommended; Manufacturer: AVX; Manufacturer_Part_Number: TCJB107M006R0040; Component_Country_Of_Origin: Lanskroun; ShowFields: YES; ID: 3896
C19 C21 C152 C157 C186 C187 C193 C204 C206 C207 = MCD-03139: Capacitor, MLCC, 22uF, 10V, X5R, +/-20%, 0805, T=1,25mm; Part_Preference: Recommended; Manufacturer: MURATA; Manufacturer_Part_Number: GRM21BR61A226ME51L; ShowFields: YES; ID: 5255; Component_Country_Of_Origin: China, Japan
C20 C29 C30 C32 C38 C184 C199 = MCD-00099: Capacitor, MLCC, 10uF, 10V, X5R, +/-10%, 0603, T=0,8mm; Manufacturer_Part_Number: GRM188R61A106KE69D; Manufacturer: MURATA; Part_Preference: Recommended; Order_Code_RS: 170-6168; Component_Country_Of_Origin: Japan; ID: 2770; ShowFields: YES
C22-C24 C26 C34-C37 C41 C200 C202 = MCD-00100: Capacitor, MLCC, 22uF, 6V3, X5R, +/-20%, 0603, T=0,8mm; Manufacturer_Part_Number: GRM188R60J226MEA0J; Manufacturer: MURATA; Part_Preference: Recommended; Component_Country_Of_Origin: Japan; ID: 2766; ShowFields: YES
C27 C28 C183 = MCD-00100: Capacitor, MLCC, 22uF, 6V3, X5R, +/-20%, 0603, T=0,8mm; Part_Preference: Recommended; Manufacturer: MURATA; Manufacturer_Part_Number: GRM188R60J226MEA0J; Component_Country_Of_Origin: Japan; ID: 2766; ShowFields: YES
C39 C43 C153 C154 C188 = MCD-00095: Capacitor, MLCC, 1uF, 25V, X5R, +/-10%, 0402, T=0.5mm; Part_Preference: Recommended; Manufacturer: MURATA; Manufacturer_Part_Number: GRM155R61E105KA12; Order_Code_RS: 846-7287; Component_Country_Of_Origin: Japan; ShowFields: YES; ID: 2772
C40 = MCD-03140: Capacitor, MLCC, 10uF, 6.3V, X5R, +/-20%, 0402, T=0.5mm; Part_Preference: Recommended; Manufacturer: MURATA; Manufacturer_Part_Number: GRM155R60J106ME05D; ShowFields: YES; ID: 5256; Component_Country_Of_Origin: China, Japan
C91 C141 C142 C156 C189 C190 C208 C209 C217 = MCD-01356: Capacitor, MLCC, 4.7uF, 6V3, X5R, +/-20%, 0402, T=0.5mm; Manufacturer_Part_Number: GRM155R60J475ME47; Manufacturer: MURATA; Part_Preference: Recommended; Order_Code_RS: 814-5230; Component_Country_Of_Origin: Japan; ShowFields: YES; ID: 3456
C155 = MCD-02198: Capacitor, MLCC, 10nF, 50V, X7R, +/-10%, 0402, T=0.5mm; Manufacturer_Part_Number: CC0402KRX7R9BB103; Manufacturer: YAGEO; Part_Preference: Recommended; Order_Code_RS: 6169644; Component_Country_Of_Origin: China; ShowFields: YES; ID: 4298
L1 L6 = MCD-03143: Inductor, 2.2uH, +/-20%, Itemp= 1700mA, Isat= 2400mA, 0R140, 0806, T=1mm; Part_Preference: Recommended; Manufacturer: MURATA; Manufacturer_Part_Number: DFE201610E-2R2M=P2; ShowFields: YES; ID: 5259; Component_Country_Of_Origin: Vietnam
L2 L4 = MCD-03142: Inductor, 0.68uH, +/-20%, Itemp= 3900mA, Isat= 5400mA, 0R031, 1008, T=1.2mm; Part_Preference: Recommended; Manufacturer: MURATA; Manufacturer_Part_Number: DFE252012F-R68M=P2; ShowFields: YES; ID: 5258; Component_Country_Of_Origin: Vietnam
L3 L5 L7 = MCD-03141: Inductor, 0.68uH, +/-20%, Itemp= 3100mA, Isat= 4300mA, 0R043, 0806, T=1mm; Part_Preference: Recommended; Manufacturer: MURATA; Manufacturer_Part_Number: DFE201610E-R68M=P2; ShowFields: YES; ID: 5257; Component_Country_Of_Origin: Vietnam
LD11 = MCD-00588: LED Green, 0603 SMD, Forward Voltage Typ=2V, Max=2.5V; Part_Type: Display; Manufacturer_Part_Number: LG Q396-PS-35; Manufacturer: OSRAM OPTO SEMICONDUCTORS; Alternate_Manufacturer_Part_Number: VLMTG1300-GS08; Alternate_Manufacturer: VISHAY SEMICONDUCTOR OPTO DIVISION; Alternate_Internal_Part_Number: MCD-02400; Part_Preference: Recommended; Provided_By: SUBCO; Component_Country_Of_Origin: Unknown; ID: 3155; ShowFields: YES
LNK1 LNK2 LNK4 LNK7 LNK8 LNK11 = MCD-02777: Track link on PCB 200um width for layout routing; Part_Preference: Recommended; Part_Type: Misc; ID: 4889; ShowFields: YES
R2 R46 R57 R59 R60 R81 = MCD-00052: Resistor,0R,0402,5%,1/16W; Manufacturer_Part_Number: RC0402JR-070RL; Manufacturer: YAGEO; Part_Preference: Recommended; ECCN_US: EAR99; ECCN_EU: NEC; Provided_By: SUBCO; Initial_Board_Reference: mb1274; Order_Code_RS: 618-5804; Component_Country_Of_Origin: China; ID: 2540; ShowFields: YES
R210 = MCD-00441: Resistor,270R,0402,1%,1/16W; Manufacturer_Part_Number: RC0402FR-07270RL; Manufacturer: YAGEO; Part_Preference: Recommended; Provided_By: SUBCO; ECCN_US: EAR99; ECCN_EU: NEC; Component_Country_Of_Origin: China; ID: 2838; ShowFields: YES
U26 = MCD-03000: STPMIC2; Part_Type: IC; Part_Preference: Recommended; Manufacturer: STMICROELECTRONICS; Component_Country_Of_Origin: Unknown; ShowFields: YES; ID: 5116

## Sheet STM32MP25XXAJ Power.SchDoc: STM32MP25XXAJ Power
size A3; Date: Not used; ApprovedBy: Not used; CheckedBy: Not used; Author: Not used; CompanyName: STMicroelectronics; DrawnBy: Not used; Engineer: Not used; Organization: Not used; Address1: Not used; Address2: Not used; Address3: Not used; Address4: Not used; DocumentNumber: 5; Revision: Not used; SheetNumber: 5; SheetTotal: 7
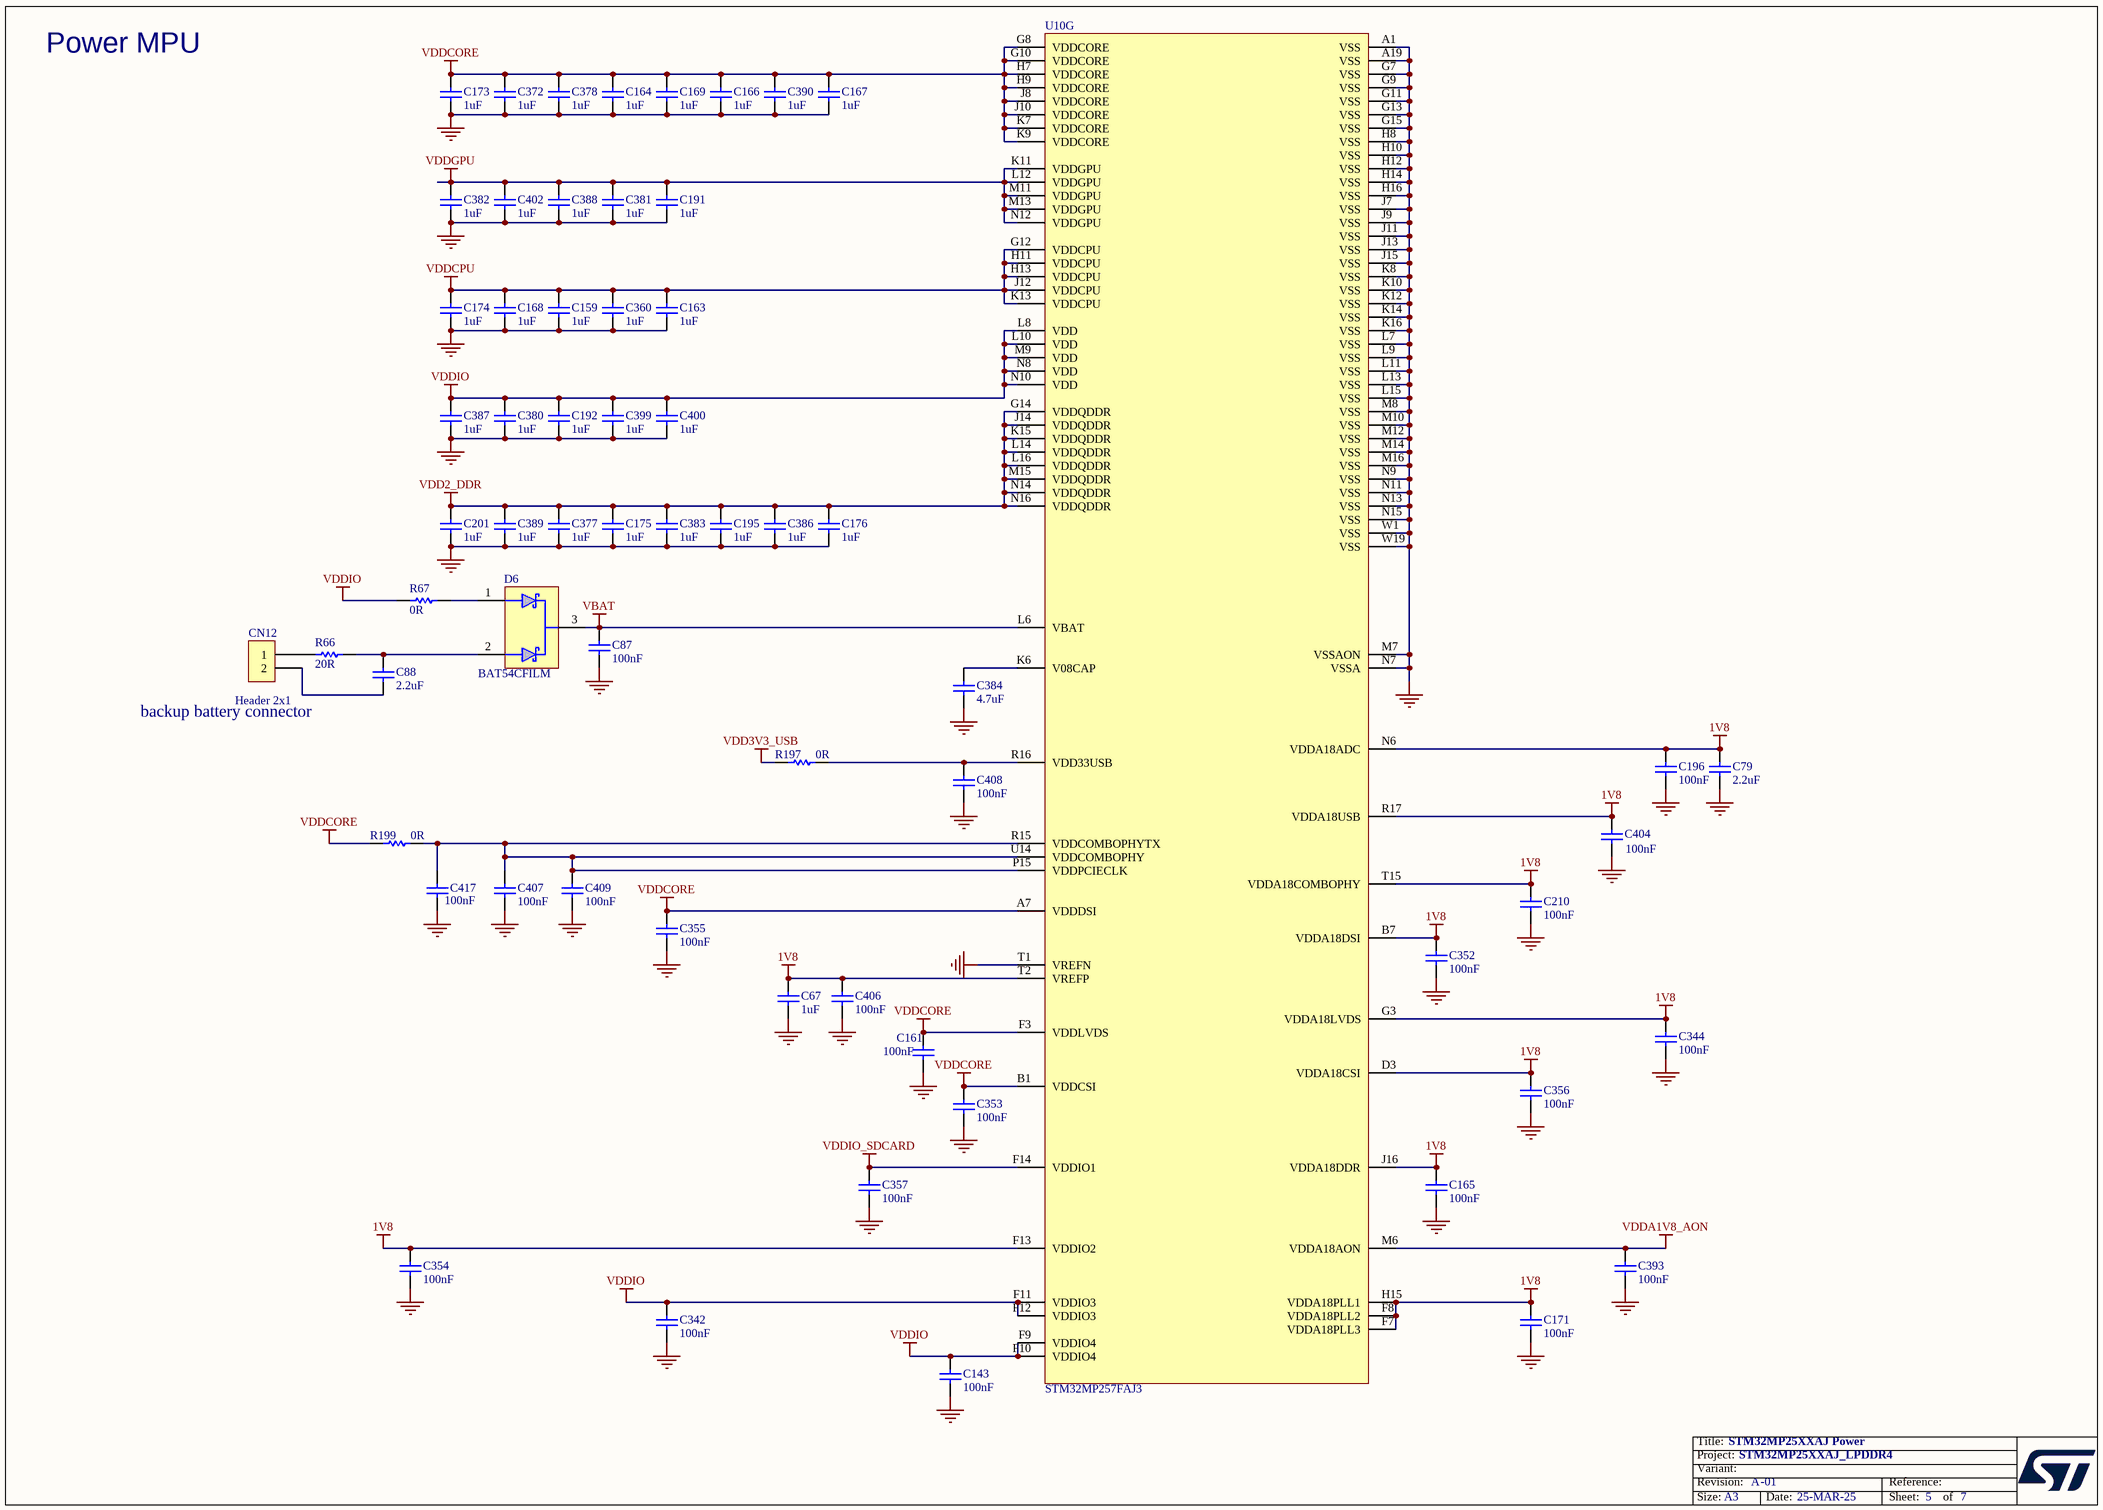
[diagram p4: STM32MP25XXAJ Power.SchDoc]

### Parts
C67  value 1uF  [C0201_MURATA_GRM033_H0P3]  (hidden comment: Capacitor)
C79  value 2.2uF  [C0201_H0P5]  (hidden comment: Capacitor)
C87  value 100nF  [C0402]
C88  value 2.2uF  [C0402]  (hidden comment: Capacitor)
C143  value 100nF  [C0201_MURATA_GRM033_H0P3]  (hidden comment: Capacitor)
C159  value 1uF  [C0201_MURATA_GRM033_H0P3]  (hidden comment: Capacitor)
C161  value 100nF  [C0201_MURATA_GRM033_H0P3]  (hidden comment: Capacitor)
C163  value 1uF  [C0201_MURATA_GRM033_H0P3]  (hidden comment: Capacitor)
C164  value 1uF  [C0201_MURATA_GRM033_H0P3]  (hidden comment: Capacitor)
C165  value 100nF  [C0201_MURATA_GRM033_H0P3]  (hidden comment: Capacitor)
C166  value 1uF  [C0201_MURATA_GRM033_H0P3]  (hidden comment: Capacitor)
C167  value 1uF  [C0201_MURATA_GRM033_H0P3]  (hidden comment: Capacitor)
C168  value 1uF  [C0201_MURATA_GRM033_H0P3]  (hidden comment: Capacitor)
C169  value 1uF  [C0201_MURATA_GRM033_H0P3]  (hidden comment: Capacitor)
C171  value 100nF  [C0201_MURATA_GRM033_H0P3]  (hidden comment: Capacitor)
C173  value 1uF  [C0201_MURATA_GRM033_H0P3]  (hidden comment: Capacitor)
C174  value 1uF  [C0201_MURATA_GRM033_H0P3]  (hidden comment: Capacitor)
C175  value 1uF  [C0201_MURATA_GRM033_H0P3]  (hidden comment: Capacitor)
C176  value 1uF  [C0201_MURATA_GRM033_H0P3]  (hidden comment: Capacitor)
C191  value 1uF  [C0201_MURATA_GRM033_H0P3]  (hidden comment: Capacitor)
C192  value 1uF  [C0201_MURATA_GRM033_H0P3]  (hidden comment: Capacitor)
C195  value 1uF  [C0201_MURATA_GRM033_H0P3]  (hidden comment: Capacitor)
C196  value 100nF  [C0201_MURATA_GRM033_H0P3]  (hidden comment: Capacitor)
C201  value 1uF  [C0201_MURATA_GRM033_H0P3]  (hidden comment: Capacitor)
C210  value 100nF  [C0201_MURATA_GRM033_H0P3]  (hidden comment: Capacitor)
C342  value 100nF  [C0201_MURATA_GRM033_H0P3]  (hidden comment: Capacitor)
C344  value 100nF  [C0201_MURATA_GRM033_H0P3]  (hidden comment: Capacitor)
C352  value 100nF  [C0201_MURATA_GRM033_H0P3]  (hidden comment: Capacitor)
C353  value 100nF  [C0201_MURATA_GRM033_H0P3]  (hidden comment: Capacitor)
C354  value 100nF  [C0201_MURATA_GRM033_H0P3]  (hidden comment: Capacitor)
C355  value 100nF  [C0201_MURATA_GRM033_H0P3]  (hidden comment: Capacitor)
C356  value 100nF  [C0201_MURATA_GRM033_H0P3]  (hidden comment: Capacitor)
C357  value 100nF  [C0201_MURATA_GRM033_H0P3]  (hidden comment: Capacitor)
C360  value 1uF  [C0201_MURATA_GRM033_H0P3]  (hidden comment: Capacitor)
C372  value 1uF  [C0201_MURATA_GRM033_H0P3]  (hidden comment: Capacitor)
C377  value 1uF  [C0201_MURATA_GRM033_H0P3]  (hidden comment: Capacitor)
C378  value 1uF  [C0201_MURATA_GRM033_H0P3]  (hidden comment: Capacitor)
C380  value 1uF  [C0201_MURATA_GRM033_H0P3]  (hidden comment: Capacitor)
C381  value 1uF  [C0201_MURATA_GRM033_H0P3]  (hidden comment: Capacitor)
C382  value 1uF  [C0201_MURATA_GRM033_H0P3]  (hidden comment: Capacitor)
C383  value 1uF  [C0201_MURATA_GRM033_H0P3]  (hidden comment: Capacitor)
C384  value 4.7uF  [C0201_H0P5]  (hidden comment: Capacitor)
C386  value 1uF  [C0201_MURATA_GRM033_H0P3]  (hidden comment: Capacitor)
C387  value 1uF  [C0201_MURATA_GRM033_H0P3]  (hidden comment: Capacitor)
C388  value 1uF  [C0201_MURATA_GRM033_H0P3]  (hidden comment: Capacitor)
C389  value 1uF  [C0201_MURATA_GRM033_H0P3]  (hidden comment: Capacitor)
C390  value 1uF  [C0201_MURATA_GRM033_H0P3]  (hidden comment: Capacitor)
C393  value 100nF  [C0201_MURATA_GRM033_H0P3]  (hidden comment: Capacitor)
C399  value 1uF  [C0201_MURATA_GRM033_H0P3]  (hidden comment: Capacitor)
C400  value 1uF  [C0201_MURATA_GRM033_H0P3]  (hidden comment: Capacitor)
C402  value 1uF  [C0201_MURATA_GRM033_H0P3]  (hidden comment: Capacitor)
C404  value 100nF  [C0201_MURATA_GRM033_H0P3]  (hidden comment: Capacitor)
C406  value 100nF  [C0201_MURATA_GRM033_H0P3]  (hidden comment: Capacitor)
C407  value 100nF  [C0201_MURATA_GRM033_H0P3]  (hidden comment: Capacitor)
C408  value 100nF  [C0201_MURATA_GRM033_H0P3]  (hidden comment: Capacitor)
C409  value 100nF  [C0201_MURATA_GRM033_H0P3]  (hidden comment: Capacitor)
C417  value 100nF  [C0201_MURATA_GRM033_H0P3]  (hidden comment: Capacitor)
CN12  value Header 2x1  [CON_MOLEX_53047-0210]
D6  value BAT54CFILM  [DIO_SOT23]  (hidden comment: DIODE_3P_DUAL_COMMON_CATHODE)
R66  value 20R  [R0402]  (hidden comment: Resistor)
R67  value 0R  [R0402]  (hidden comment: Resistor)
R197  value 0R  [R0402]
R199  value 0R  [R0402]
U10  value STM32MP257FAJ3  [ICC_TFBGA361_16X16_P080]  (hidden comment: IC_STM32MP257FAJ3)  (part G of 9)

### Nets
1V8: C67.2 C79.2 C165.2 C171.2 C196.2 C210.2 C344.2 C352.2 C354.2 C356.2 C404.2 C406.2 U10.B7(VDDA18DSI) U10.D3(VDDA18CSI) U10.F7(VDDA18PLL3) U10.F8(VDDA18PLL2) U10.F13(VDDIO2) U10.G3(VDDA18LVDS) U10.H15(VDDA18PLL1) U10.J16(VDDA18DDR) U10.N6(VDDA18ADC) U10.R17(VDDA18USB) U10.T2(VREFP) U10.T15(VDDA18COMBOPHY)
GND: C67.1 C79.1 C87.1 C143.1 C159.1 C161.1 C163.1 C164.2 C165.1 C166.1 C167.1 C168.1 C169.1 C171.1 C173.2 C174.2 C175.1 C176.1 C191.2 C192.1 C195.1 C196.1 C201.1 C210.1 C342.1 C344.1 C352.1 C353.1 C354.1 C355.1 C356.1 C357.1 C360.2 C372.1 C377.1 C378.1 C380.1 C381.1 C382.1 C383.1 C384.1 C386.1 C387.2 C388.1 C389.2 C390.1 C393.1 C399.2 C400.1 C402.1 C404.1 C406.1 C407.1 C408.1 C409.1 C417.1 U10.A1(VSS) U10.A19(VSS) U10.G7(VSS) U10.G9(VSS) U10.G11(VSS) U10.G13(VSS) U10.G15(VSS) U10.H8(VSS) U10.H10(VSS) U10.H12(VSS) U10.H14(VSS) U10.H16(VSS) U10.J7(VSS) U10.J9(VSS) U10.J11(VSS) U10.J13(VSS) U10.J15(VSS) U10.K8(VSS) U10.K10(VSS) U10.K12(VSS) U10.K14(VSS) U10.K16(VSS) U10.L7(VSS) U10.L9(VSS) U10.L11(VSS) U10.L13(VSS) U10.L15(VSS) U10.M7(VSSAON) U10.M8(VSS) U10.M10(VSS) U10.M12(VSS) U10.M14(VSS) U10.M16(VSS) U10.N7(VSSA) U10.N9(VSS) U10.N11(VSS) U10.N13(VSS) U10.N15(VSS) U10.T1(VREFN) U10.W1(VSS) U10.W19(VSS)
VBAT: C87.2 D6.3 U10.L6(VBAT)
VDD2_DDR: C175.2 C176.2 C195.2 C201.2 C377.2 C383.2 C386.2 C389.1 U10.G14(VDDQDDR) U10.J14(VDDQDDR) U10.K15(VDDQDDR) U10.L14(VDDQDDR) U10.L16(VDDQDDR) U10.M15(VDDQDDR) U10.N14(VDDQDDR) U10.N16(VDDQDDR)
VDD3V3_USB: R197.1
VDDA1V8_AON: C393.2 U10.M6(VDDA18AON)
VDDCORE: C161.2 C164.1 C166.2 C167.2 C169.2 C173.1 C353.2 C355.2 C372.2 C378.2 C390.2 R199.1 U10.A7(VDDDSI) U10.B1(VDDCSI) U10.F3(VDDLVDS) U10.G8(VDDCORE) U10.G10(VDDCORE) U10.H7(VDDCORE) U10.H9(VDDCORE) U10.J8(VDDCORE) U10.J10(VDDCORE) U10.K7(VDDCORE) U10.K9(VDDCORE)
VDDCPU: C159.2 C163.2 C168.2 C174.1 C360.1 U10.G12(VDDCPU) U10.H11(VDDCPU) U10.H13(VDDCPU) U10.J12(VDDCPU) U10.K13(VDDCPU)
VDDGPU: C191.1 C381.2 C382.2 C388.2 C402.2 U10.K11(VDDGPU) U10.L12(VDDGPU) U10.M11(VDDGPU) U10.M13(VDDGPU) U10.N12(VDDGPU)
VDDIO: C143.2 C192.2 C342.2 C380.2 C387.1 C399.1 C400.2 R67.2 U10.F9(VDDIO4) U10.F10(VDDIO4) U10.F11(VDDIO3) U10.F12(VDDIO3) U10.L8(VDD) U10.L10(VDD) U10.M9(VDD) U10.N8(VDD) U10.N10(VDD)
VDDIO_SDCARD: C357.2 U10.F14(VDDIO1)
NetC88_1: C88.1 CN12.2
NetC88_2: C88.2 D6.2 R66.2
NetC384_2: C384.2 U10.K6(V08CAP)
NetC407_2: C407.2 C409.2 C417.2 R199.2 U10.P15(VDDPCIECLK) U10.R15(VDDCOMBOPHYTX) U10.U14(VDDCOMBOPHY)
NetC408_2: C408.2 R197.2 U10.R16(VDD33USB)
NetCN12_1: CN12.1 R66.1
NetD6_1: D6.1 R67.1

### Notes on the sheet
- Power MPU
- backup battery connector

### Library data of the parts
C67 = MCD-02377: Capacitor, MLCC, 1uF, 6.3V, X5R, +/-20%, 0201, T=0,3mm; Manufacturer_Part_Number: GRM033R60J105MEA2; Manufacturer: MURATA; Part_Preference: Recommended; Order_Code_RS: 820-0643; Component_Country_Of_Origin: Japan°; ID: 4483; ShowFields: YES
C79 = MCD-02235: Capacitor, MLCC, 2.2uF, 10V, X5R,+/-10%, 0201, T=0.5mm; Part_Preference: Recommended; Manufacturer: MURATA; Manufacturer_Part_Number: GRM033R61A225KE47D; Order_Code_RS: NA; Component_Country_Of_Origin: Japan°°; ShowFields: YES; ID: 4335
C87 = MCD-00006: Capacitor,100nF,16V,X7R,10%,0402; Manufacturer_Part_Number: CC0402KRX7R7BB104; Manufacturer: YAGEO; Alternate_Manufacturer: MURATA; Alternate_Manufacturer_Part_Number: GCM155R71C104KA55D; Part_Preference: Recommended; Partial_Alternate_Internal_Part_Number: MCD-03299; Provided_By: SUBCO; Initial_Board_Reference: MB1274; Order_Code_RS: 9402047; Component_Country_Of_Origin: China; ID: 2474; ShowFields: YES
C88 = MCD-01823: Capacitor, MLCC, 2.2uF, 6V3, X5R,+/-10%, 0402, T=0.5mm; Part_Preference: Recommended; Manufacturer: MURATA; Manufacturer_Part_Number: GRM155R60J225KE95D; Partial_Alternate_Internal_Part_Number: MCD-03566; Order_Code_RS: 172-6478; Component_Country_Of_Origin: Japan°°; ID: 3923; ShowFields: YES
C143 C161 C165 C171 C196 C210 C342 C344 C352-C357 C393 C404 C406-C409 C417 = MCD-01535: Capacitor, MLCC,100nF, 10V, X7R, +/-10%, 0201, T=0.3mm; Part_Preference: Recommended; Manufacturer: MURATA; Manufacturer_Part_Number: GRM033R61A104KE15; Order_Code_RS: 790-2742
C159 C163 C164 C166-C169 C173-C176 C191 C192 C195 C201 C360 C372 C377 C378 C380-C383 C386-C390 C399 C400 C402 = MCD-02377: Capacitor, MLCC, 1uF, 6.3V, X5R, +/-20%, 0201, T=0,3mm; Manufacturer_Part_Number: GRM033R60J105MEA2; Manufacturer: MURATA; Part_Preference: Recommended; Order_Code_RS: 820-0643
C384 = MCD-01534: Capacitor, MLCC, 4,7uF, 6V3, X5R, +/-20%, 0201, T=0.5mm; Part_Preference: Recommended; Manufacturer: MURATA; Manufacturer_Part_Number: GRM035R60J475ME15
CN12 = MCD-00655: Header 2 circuits, 1.25mm Pitch ,  Vertical, with Friction Lock; Part_Type: Connector; Manufacturer_Part_Number: 53047-0210; Manufacturer: MOLEX; BMS_Part_Number: 9083002; Part_Preference: Recommended; Provided_By: SUBCO; Initial_Board_Reference: MB1272; Order_Code_RS: 279-9213; Component_Country_Of_Origin: Unknown; ID: 3091; ShowFields: YES
D6 = MCD-03280: Diode, Schottky, Dual Common Cathode, 0V3, 300mA, 40V, SOT-23; Part_Preference: Recommended; Manufacturer: STMICROELECTRONICS; Order_code_RS: 795-8397; Component_Country_Of_Origin: China; ShowFields: YES; ID: 5396
R66 = MCD-00058: Resistor, 20R, 0402, +/-1%, 1/16W; BMS_Part_Number: 9131027; Part_Preference: Recommended; Manufacturer: YAGEO; Manufacturer_Part_Number: RC0402FR-0720RL; Order_Code_RS: 1799192; Component_Country_Of_Origin: China; ID: 2537; ShowFields: YES
R67 = MCD-00052: Resistor, 0R, 0402, +/-5%, 1/16W; Manufacturer_Part_Number: RC0402JR-070RL; Manufacturer: YAGEO; Part_Preference: Recommended; Order_Code_RS: 9232516RL; Component_Country_Of_Origin: China; ShowFields: YES; ID: 2540
R197 R199 = MCD-00052: Resistor,0R,0402,5%,1/16W; Manufacturer_Part_Number: RC0402JR-070RL; Manufacturer: YAGEO; Part_Preference: Recommended; ECCN_US: EAR99; ECCN_EU: NEC; Provided_By: SUBCO; Initial_Board_Reference: mb1274; Order_Code_RS: 618-5804
U10 = MCD-04441: as U10 on sheet STM32MP25XXAJ I_Os

## Sheet eMMC.SchDoc: eMMC
size A3; Date: Not used; ApprovedBy: Not used; CheckedBy: Not used; Author: Not used; CompanyName: STMicroelectronics; DrawnBy: Not used; Engineer: Not used; Organization: Not used; Address1: Not used; Address2: Not used; Address3: Not used; Address4: Not used; DocumentNumber: 7; Revision: Not used; SheetNumber: 7; SheetTotal: 7
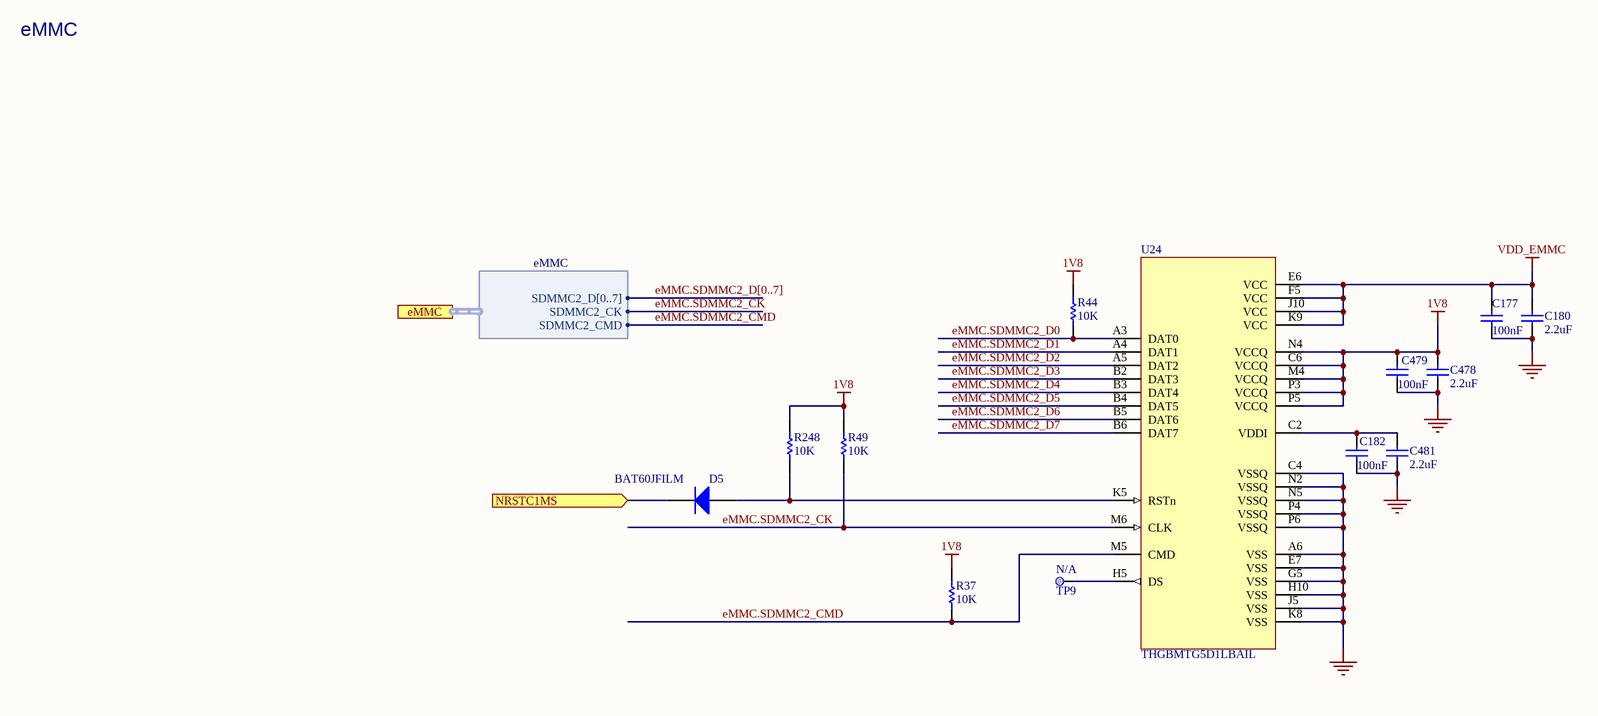
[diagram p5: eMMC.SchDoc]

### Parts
C177  value 100nF  [C0402]  (hidden comment: Capacitor)
C180  value 2.2uF  [C0402]  (hidden comment: Capacitor)
C182  value 100nF  [C0402]  (hidden comment: Capacitor)
C478  value 2.2uF  [C0402]  (hidden comment: Capacitor)
C479  value 100nF  [C0402]  (hidden comment: Capacitor)
C481  value 2.2uF  [C0402]  (hidden comment: Capacitor)
D5  BAT60JFILM  [DIO_SOD323]
R37  value 10K  [R0402]  (hidden comment: Resistor)
R44  value 10K  [R0402]  (hidden comment: Resistor)
R49  value 10K  [R0402]  (hidden comment: Resistor)
R248  value 10K  [R0402]  (hidden comment: Resistor)
TP9  Test Point  [TP_SMD_1MM]  (value not drawn)  (no BOM)
U24  value THGBMTG5D1LBAIL  [ICC_P-WFBGA153_13X11P5_P050]  (hidden comment: eMMC_THGBMTG5D1LBAIL)

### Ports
eMMC (harness eMMC), NRSTC1MS (in)

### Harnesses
eMMC: SDMMC2_CK, SDMMC2_CMD, SDMMC2_D[0..7]

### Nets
1V8: C478.2 C479.2 R37.2 R44.2 R49.2 R248.2 U24.C6(VCCQ) U24.M4(VCCQ) U24.N4(VCCQ) U24.P3(VCCQ) U24.P5(VCCQ)
GND: C177.1 C180.1 C182.1 C478.1 C479.1 C481.1 U24.A6(VSS) U24.C4(VSSQ) U24.E7(VSS) U24.G5(VSS) U24.H10(VSS) U24.J5(VSS) U24.K8(VSS) U24.N2(VSSQ) U24.N5(VSSQ) U24.P4(VSSQ) U24.P6(VSSQ)
VDD_EMMC: C177.2 C180.2 U24.E6(VCC) U24.F5(VCC) U24.J10(VCC) U24.K9(VCC)
eMMC.SDMMC2_CK: R49.1 U24.M6(CLK) ; port eMMC.SDMMC2_CK
eMMC.SDMMC2_CMD: R37.1 U24.M5(CMD) ; port eMMC.SDMMC2_CMD
eMMC.SDMMC2_D0: R44.1 U24.A3(DAT0)
eMMC.SDMMC2_D1: U24.A4(DAT1)
eMMC.SDMMC2_D2: U24.A5(DAT2)
eMMC.SDMMC2_D3: U24.B2(DAT3)
eMMC.SDMMC2_D4: U24.B3(DAT4)
eMMC.SDMMC2_D5: U24.B4(DAT5)
eMMC.SDMMC2_D6: U24.B5(DAT6)
eMMC.SDMMC2_D7: U24.B6(DAT7)
NRSTC1MS: D5.2(K) ; port NRSTC1MS
NetC182_2: C182.2 C481.2 U24.C2(VDDI)
NetD5_1: D5.1(A) R248.1 U24.K5(RSTn)
NetTP9_1: TP9.1 U24.H5(DS)

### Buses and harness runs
bus eMMC.SDMMC2_D[0..7]

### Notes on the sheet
- eMMC

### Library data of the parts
C177 C182 C479 = MCD-00006: Capacitor, MLCC, 100nF, 16V, X7R, +/-10%, 0402, T=0.5mm; Part_Preference: Recommended; Manufacturer: YAGEO; Manufacturer_Part_Number: CC0402KRX7R7BB104; Alternate_Manufacturer: MURATA; Alternate_Manufacturer_Part_Number: GCM155R71C104KA55D; Partial_Alternate_Internal_Part_Number: MCD-03299; Order_Code_RS: 9402047; Component_Country_Of_Origin: China; ID: 2474; ShowFields: YES
C180 C478 C481 = MCD-02606: Capacitor, MLCC, 2.2uF, 6.3V, X5R, +/-10%, 0402, T=0.5mm; Part_Preference: Recommended; Manufacturer: YAGEO; Manufacturer_Part_Number: CC0402KRX5R5BB225; Order_Code_RS: 1992205; ShowFields: YES; ID: 4712; Component_Country_Of_Origin: China°
D5 = MCD-00034: BMS_Part_Number: 9151097; Part_Type: Diode; Part_Preference: Recommended; Manufacturer: STMICROELECTRONICS; Manufacturer_HQ_COO: EU; Component_Country_Of_Origin: China; ShowFields: YES; ID: 2483; Order_Code_RS: 714-6879
R37 R44 R49 R248 = MCD-00053: Resistor,10K,0402,1%,1/16W; Manufacturer_Part_Number: RC0402FR-0710KL; Manufacturer: YAGEO; BMS_Part_Number: 9131590; Part_Preference: Recommended; ECCN_US: EAR99; ECCN_EU: NEC; Provided_By: SUBCO; Order_Code_RS: 9239359; Component_Country_Of_Origin: China; ID: 2539; ShowFields: YES
TP9 = MCD-00074: Test Point 1mm; Part_Type: Misc; Part_Preference: Recommended; Component_Country_Of_Origin: Unknown; ID: 2518; ShowFields: YES
U24 = MCD-02799: Memory, eMMC, 4GB, 15nm ,WFBGA , 153 pins; Part_Type: IC; Part_Preference: Not recommended; Manufacturer: KIOXIA; ShowFields: YES; ID: 4911; Component_Country_Of_Origin: Unknown

## Sheet LPDDR4_16bits.SchDoc: LPDDR4_16bits
size A3; Date: Not used; ApprovedBy: Not used; CheckedBy: Not used; Author: Not used; CompanyName: STMicroelectronics; DrawnBy: Not used; Engineer: Not used; Organization: Not used; Address1: Not used; Address2: Not used; Address3: Not used; Address4: Not used; DocumentNumber: 6; Revision: Not used; SheetNumber: 6; SheetTotal: 7
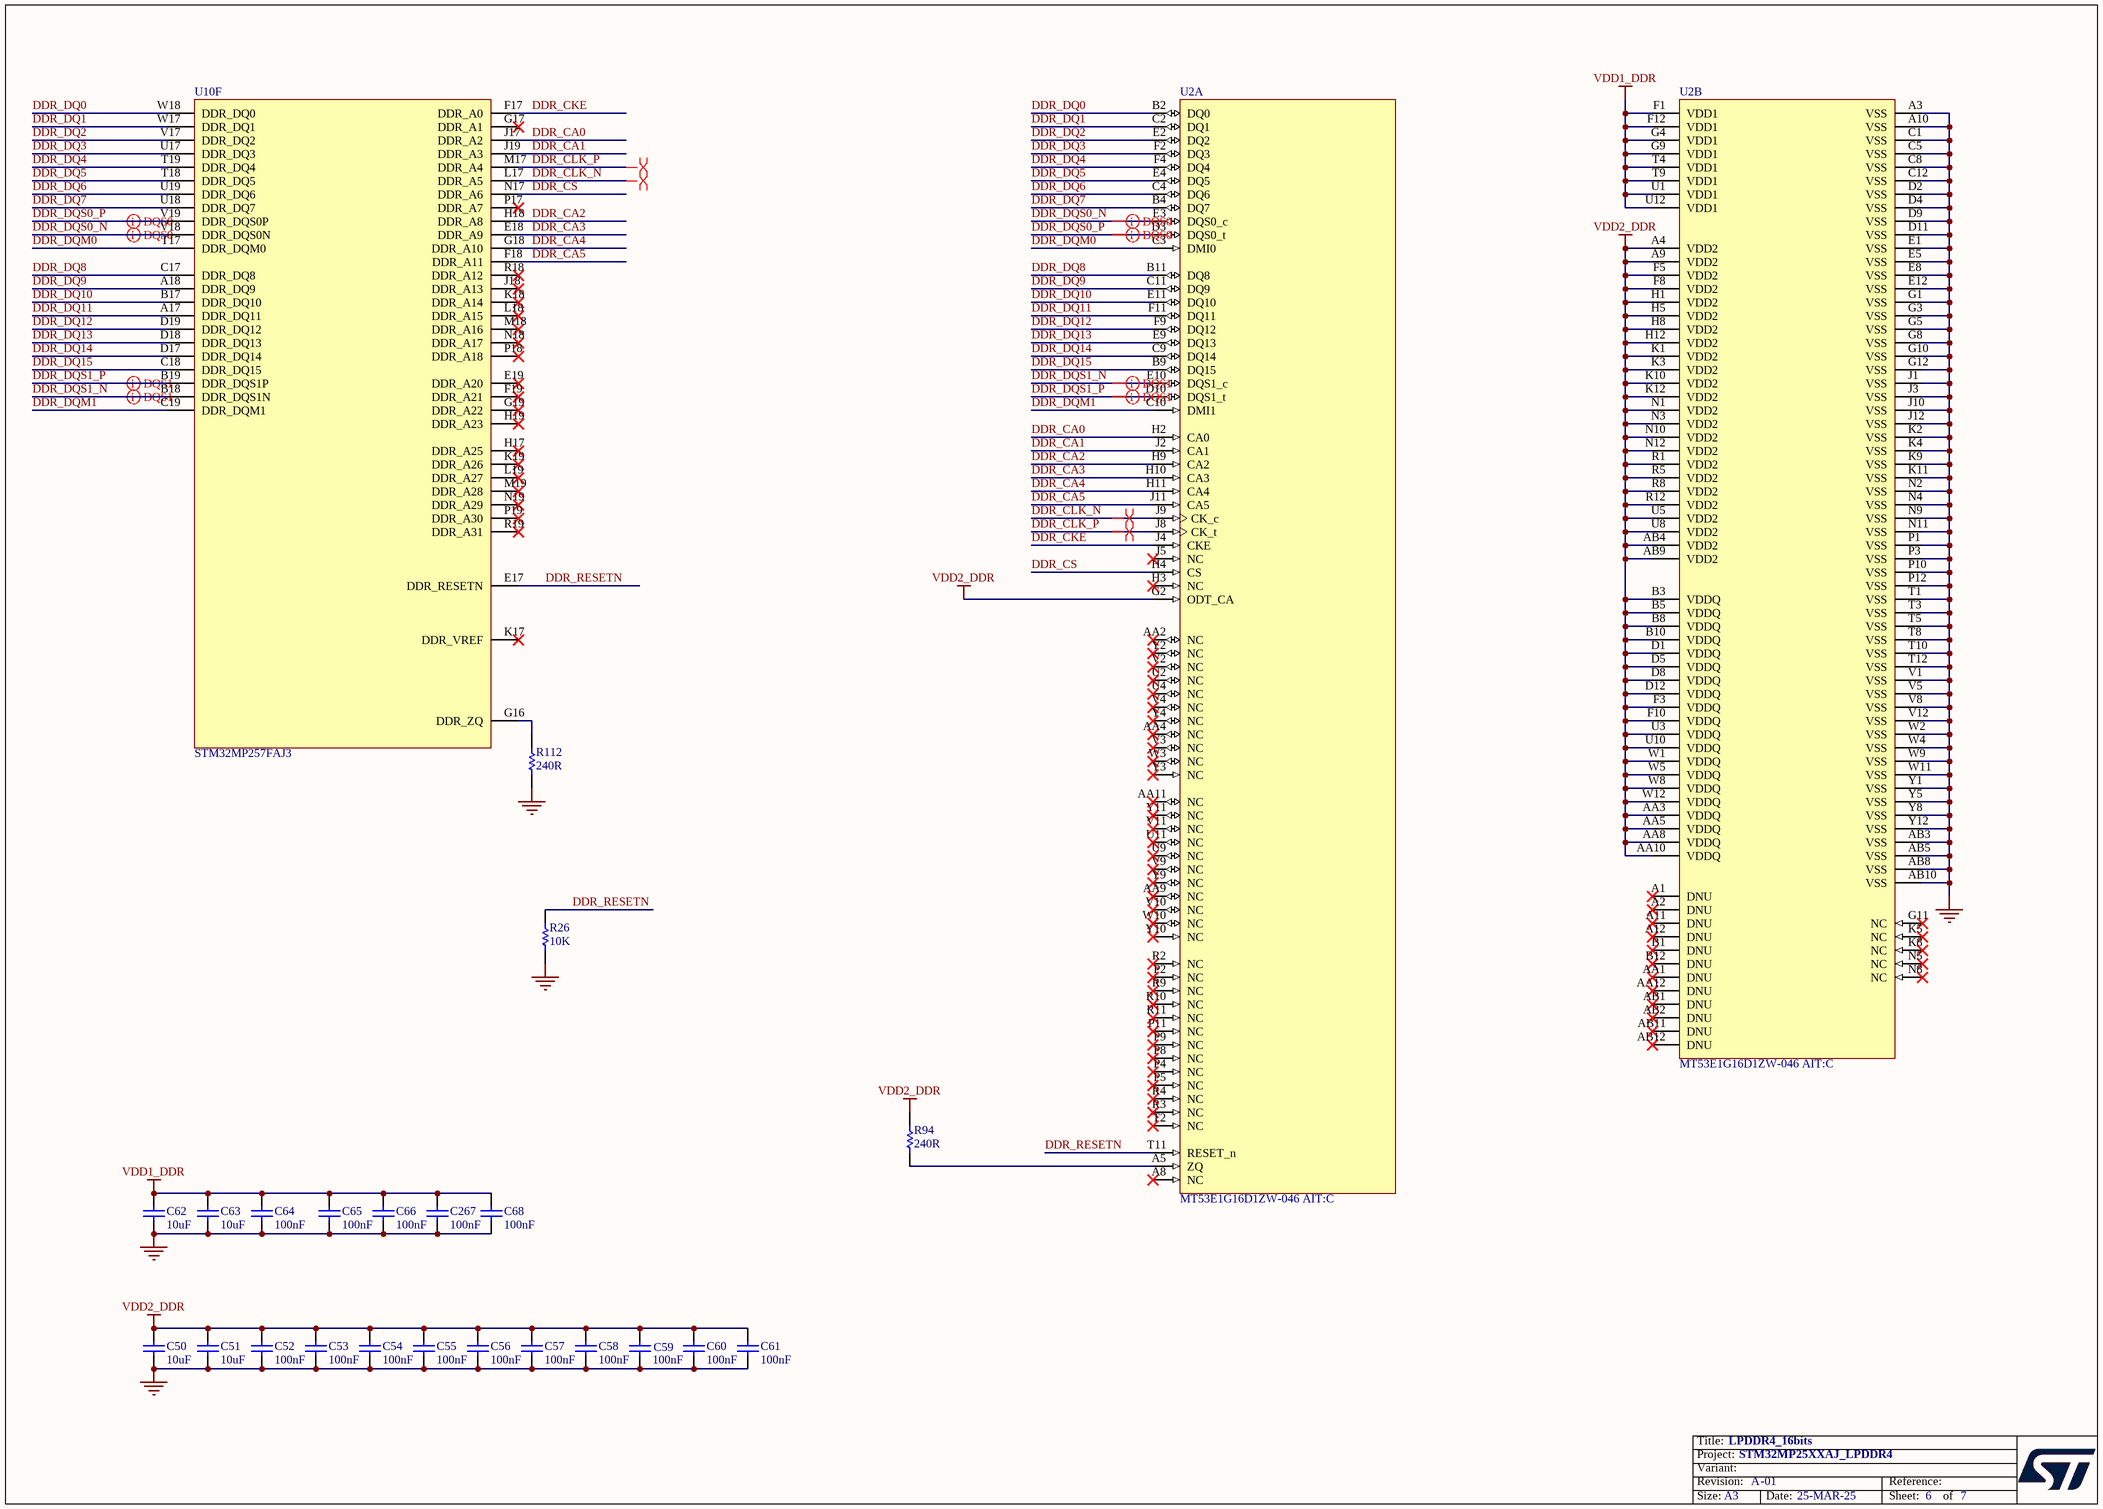
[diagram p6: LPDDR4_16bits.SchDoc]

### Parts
C50  value 10uF  [C0603]  (hidden comment: Capacitor)
C51  value 10uF  [C0603]  (hidden comment: Capacitor)
C52  value 100nF  [C0402]  (hidden comment: Capacitor)
C53  value 100nF  [C0402]  (hidden comment: Capacitor)
C54  value 100nF  [C0402]  (hidden comment: Capacitor)
C55  value 100nF  [C0402]  (hidden comment: Capacitor)
C56  value 100nF  [C0402]  (hidden comment: Capacitor)
C57  value 100nF  [C0402]  (hidden comment: Capacitor)
C58  value 100nF  [C0402]  (hidden comment: Capacitor)
C59  value 100nF  [C0402]  (hidden comment: Capacitor)
C60  value 100nF  [C0402]  (hidden comment: Capacitor)
C61  value 100nF  [C0402]  (hidden comment: Capacitor)
C62  value 10uF  [C0603]  (hidden comment: Capacitor)
C63  value 10uF  [C0603]  (hidden comment: Capacitor)
C64  value 100nF  [C0402]  (hidden comment: Capacitor)
C65  value 100nF  [C0402]  (hidden comment: Capacitor)
C66  value 100nF  [C0402]  (hidden comment: Capacitor)
C68  value 100nF  [C0402]  (hidden comment: Capacitor)
C267  value 100nF  [C0402]  (hidden comment: Capacitor)
R26  value 10K  [R0402]  (hidden comment: Resistor)
R94  value 240R  [R0201_H0P23]  (hidden comment: Resistor)
R112  value 240R  [R0201_H0P23]  (hidden comment: Resistor)
U2  MT53E1G16D1ZW-046 AIT:C  [ICC_TFBGA200_10X14P5_P080_H1P05]  (parts A,B of 2)
U10  value STM32MP257FAJ3  [ICC_TFBGA361_16X16_P080]  (hidden comment: IC_STM32MP257FAJ3)  (part F of 9)

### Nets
GND: C50.1 C51.1 C52.1 C53.2 C54.2 C55.2 C56.2 C57.2 C58.2 C59.2 C60.2 C61.2 C62.1 C63.1 C64.1 C65.1 C66.1 C68.1 C267.1 R26.1 R112.1 U2.A3(VSS) U2.A10(VSS) U2.AB3(VSS) U2.AB5(VSS) U2.AB8(VSS) U2.AB10(VSS) U2.C1(VSS) U2.C5(VSS) U2.C8(VSS) U2.C12(VSS) U2.D2(VSS) U2.D4(VSS) U2.D9(VSS) U2.D11(VSS) U2.E1(VSS) U2.E5(VSS) U2.E8(VSS) U2.E12(VSS) U2.G1(VSS) U2.G3(VSS) U2.G5(VSS) U2.G8(VSS) U2.G10(VSS) U2.G12(VSS) U2.J1(VSS) U2.J3(VSS) U2.J10(VSS) U2.J12(VSS) U2.K2(VSS) U2.K4(VSS) U2.K9(VSS) U2.K11(VSS) U2.N2(VSS) U2.N4(VSS) U2.N9(VSS) U2.N11(VSS) U2.P1(VSS) U2.P3(VSS) U2.P10(VSS) U2.P12(VSS) U2.T1(VSS) U2.T3(VSS) U2.T5(VSS) U2.T8(VSS) U2.T10(VSS) U2.T12(VSS) U2.V1(VSS) U2.V5(VSS) U2.V8(VSS) U2.V12(VSS) U2.W2(VSS) U2.W4(VSS) U2.W9(VSS) U2.W11(VSS) U2.Y1(VSS) U2.Y5(VSS) U2.Y8(VSS) U2.Y12(VSS)
VDD1_DDR: C62.2 C63.2 C64.2 C65.2 C66.2 C68.2 C267.2 U2.F1(VDD1) U2.F12(VDD1) U2.G4(VDD1) U2.G9(VDD1) U2.T4(VDD1) U2.T9(VDD1) U2.U1(VDD1) U2.U12(VDD1)
VDD2_DDR: C50.2 C51.2 C52.2 C53.1 C54.1 C55.1 C56.1 C57.1 C58.1 C59.1 C60.1 C61.1 R94.2 U2.A4(VDD2) U2.A9(VDD2) U2.AA3(VDDQ) U2.AA5(VDDQ) U2.AA8(VDDQ) U2.AA10(VDDQ) U2.AB4(VDD2) U2.AB9(VDD2) U2.B3(VDDQ) U2.B5(VDDQ) U2.B8(VDDQ) U2.B10(VDDQ) U2.D1(VDDQ) U2.D5(VDDQ) U2.D8(VDDQ) U2.D12(VDDQ) U2.F3(VDDQ) U2.F5(VDD2) U2.F8(VDD2) U2.F10(VDDQ) U2.G2(ODT_CA) U2.H1(VDD2) U2.H5(VDD2) U2.H8(VDD2) U2.H12(VDD2) U2.K1(VDD2) U2.K3(VDD2) U2.K10(VDD2) U2.K12(VDD2) U2.N1(VDD2) U2.N3(VDD2) U2.N10(VDD2) U2.N12(VDD2) U2.R1(VDD2) U2.R5(VDD2) U2.R8(VDD2) U2.R12(VDD2) U2.U3(VDDQ) U2.U5(VDD2) U2.U8(VDD2) U2.U10(VDDQ) U2.W1(VDDQ) U2.W5(VDDQ) U2.W8(VDDQ) U2.W12(VDDQ)
DDR_CA0: U2.H2(CA0) U10.J17(DDR_A2)
DDR_CA1: U2.J2(CA1) U10.J19(DDR_A3)
DDR_CA2: U2.H9(CA2) U10.H18(DDR_A8)
DDR_CA3: U2.H10(CA3) U10.E18(DDR_A9)
DDR_CA4: U2.H11(CA4) U10.G18(DDR_A10)
DDR_CA5: U2.J11(CA5) U10.F18(DDR_A11)
DDR_CKE: U2.J4(CKE) U10.F17(DDR_A0)
DDR_CLK_N: U2.J9(CK_c) U10.L17(DDR_A5)
DDR_CLK_P: U2.J8(CK_t) U10.M17(DDR_A4)
DDR_CS: U2.H4(CS) U10.N17(DDR_A6)
DDR_DQ0: U2.B2(DQ0) U10.W18(DDR_DQ0)
DDR_DQ1: U2.C2(DQ1) U10.W17(DDR_DQ1)
DDR_DQ2: U2.E2(DQ2) U10.V17(DDR_DQ2)
DDR_DQ3: U2.F2(DQ3) U10.U17(DDR_DQ3)
DDR_DQ4: U2.F4(DQ4) U10.T19(DDR_DQ4)
DDR_DQ5: U2.E4(DQ5) U10.T18(DDR_DQ5)
DDR_DQ6: U2.C4(DQ6) U10.U19(DDR_DQ6)
DDR_DQ7: U2.B4(DQ7) U10.U18(DDR_DQ7)
DDR_DQ8: U2.B11(DQ8) U10.C17(DDR_DQ8)
DDR_DQ9: U2.C11(DQ9) U10.A18(DDR_DQ9)
DDR_DQ10: U2.E11(DQ10) U10.B17(DDR_DQ10)
DDR_DQ11: U2.F11(DQ11) U10.A17(DDR_DQ11)
DDR_DQ12: U2.F9(DQ12) U10.D19(DDR_DQ12)
DDR_DQ13: U2.E9(DQ13) U10.D18(DDR_DQ13)
DDR_DQ14: U2.C9(DQ14) U10.D17(DDR_DQ14)
DDR_DQ15: U2.B9(DQ15) U10.C18(DDR_DQ15)
DDR_DQM0: U2.C3(DMI0) U10.T17(DDR_DQM0)
DDR_DQM1: U2.C10(DMI1) U10.C19(DDR_DQM1)
DDR_DQS0_N: U2.E3(DQS0_c) U10.V18(DDR_DQS0N)
DDR_DQS0_P: U2.D3(DQS0_t) U10.V19(DDR_DQS0P)
DDR_DQS1_N: U2.E10(DQS1_c) U10.B18(DDR_DQS1N)
DDR_DQS1_P: U2.D10(DQS1_t) U10.B19(DDR_DQS1P)
DDR_RESETN: R26.2 U2.T11(RESET_n) U10.E17(DDR_RESETN)
NetR94_1: R94.1 U2.A5(ZQ)
NetR112_2: R112.2 U10.G16(DDR_ZQ)

Not connected (* = marked no-connect by the designer): U2 A1(DNU)* A2(DNU)* A8(NC)* A11(DNU)* A12(DNU)* AA1(DNU)* AA2(NC)* AA4(NC)* AA9(NC)* AA11(NC)* AA12(DNU)* AB1(DNU)* AB2(DNU)* AB11(DNU)* AB12(DNU)* B1(DNU)* B12(DNU)* G11(NC)* H3(NC)* J5(NC)* K5(NC)* K8(NC)* N5(NC)* N8(NC)* P2(NC)* P4(NC)* P5(NC)* P8(NC)* P9(NC)* P11(NC)* R2(NC)* R3(NC)* R4(NC)* R9(NC)* R10(NC)* R11(NC)* T2(NC)* U2(NC)* U4(NC)* U9(NC)* U11(NC)* V2(NC)* V3(NC)* V4(NC)* V9(NC)* V10(NC)* V11(NC)* W3(NC)* W10(NC)* Y2(NC)* Y3(NC)* Y4(NC)* Y9(NC)* Y10(NC)* Y11(NC)*; U10 E19(DDR_A20)* F19(DDR_A21)* G17(DDR_A1)* G19(DDR_A22)* H17(DDR_A25)* H19(DDR_A23)* J18(DDR_A13)* K17(DDR_VREF)* K18(DDR_A14)* K19(DDR_A26)* L18(DDR_A15)* L19(DDR_A27)* M18(DDR_A16)* M19(DDR_A28)* N18(DDR_A17)* N19(DDR_A29)* P17(DDR_A7)* P18(DDR_A18)* P19(DDR_A30)* R18(DDR_A12)* R19(DDR_A31)*

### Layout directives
differential pair: DDR_CLK_N, DDR_CLK_P, DDR_DQS0_N, DDR_DQS0_P, DDR_DQS1_N, DDR_DQS1_P

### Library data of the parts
C50 C51 C62 C63 = MCD-01341: Capacitor, MLCC, 10uF, 6V3, X5R, +/-20%, 0603, T=0.8mm; Part_Preference: Recommended; Manufacturer: MURATA; Manufacturer_Part_Number: GRM188R60J106ME47D; Component_Country_Of_Origin: Japan°°; ShowFields: YES; ID: 3441
C52-C61 C64-C66 C68 C267 = MCD-00006: Capacitor, MLCC, 100nF, 16V, X7R, +/-10%, 0402, T=0.5mm; Part_Preference: Recommended; Manufacturer: YAGEO; Manufacturer_Part_Number: CC0402KRX7R7BB104; Partial_Alternate_Internal_Part_Number: MCD-03299; Order_Code_RS: 9402047; Component_Country_Of_Origin: China; ShowFields: YES; ID: 2474
R26 = MCD-00053: Resistor, 10K, 0402, +/-1%, 1/16W; BMS_Part_Number: 9131590; Part_Preference: Recommended; Manufacturer: YAGEO; Manufacturer_Part_Number: RC0402FR-0710KL; Order_Code_RS: 9239359; Component_Country_Of_Origin: China; ShowFields: YES; ID: 2539
R94 = MCD-02253: Resistor, 240R, 0201, +/-1%, 1/20W; Part_Preference: Recommended; Manufacturer: YAGEO; Manufacturer_Part_Number: RC0201FR-07240RL; Component_Country_Of_Origin: China; ShowFields: YES; ID: 4353
R112 = MCD-02253: Resistor,240R,0201,1%,1/20W; Part_Preference: Recommended; Manufacturer: YAGEO; Manufacturer_Part_Number: RC0201FR-07240RL
U2 = MCD-04012: Memory, SDRAM, 1V1, 16Gbit, 4266MHz; Part_Type: IC; Part_Preference: Recommended; Manufacturer: MICRON; Component_Country_Of_Origin: Taiwan°; ShowFields: YES; ID: 6128
U10 = MCD-04441: as U10 on sheet STM32MP25XXAJ I_Os

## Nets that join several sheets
1V8: PMIC (5 pins), STM32MP25XXAJ Power (24 pins), eMMC (11 pins)
GND: STM32MP25XXAJ I_Os (10 pins), PMIC (62 pins), STM32MP25XXAJ Power (97 pins), eMMC (17 pins), LPDDR4_16bits (79 pins)
VDD1_DDR: PMIC (C40.2 U26.44), LPDDR4_16bits (15 pins)
VDD2_DDR: PMIC (5 pins), STM32MP25XXAJ Power (16 pins), LPDDR4_16bits (58 pins)
VDD3V3_USB: PMIC (C156.2 U26.13), STM32MP25XXAJ Power (R197.1)
VDD_EMMC: PMIC (C190.1 U26.16), eMMC (6 pins)
VDDA1V8_AON: STM32MP25XXAJ I_Os (U10.P1), PMIC (C189.2 U26.14), STM32MP25XXAJ Power (C393.2 U10.M6)
VDDCORE: PMIC (6 pins), STM32MP25XXAJ Power (23 pins)
VDDCPU: PMIC (5 pins), STM32MP25XXAJ Power (10 pins)
VDDGPU: PMIC (6 pins), STM32MP25XXAJ Power (10 pins)
VDDIO: STM32MP25XXAJ I_Os (R27.2 R260.2 R261.2), PMIC (6 pins), STM32MP25XXAJ Power (17 pins)
VDDIO_SDCARD: PMIC (C217.1 U26.2), STM32MP25XXAJ Power (C357.2 U10.F14)
eMMC.SDMMC2_CK: STM32MP25XXAJ I_Os (U10.F15), eMMC (R49.1 U24.M6)
eMMC.SDMMC2_CMD: STM32MP25XXAJ I_Os (U10.F16), eMMC (R37.1 U24.M5)
eMMC.SDMMC2_D0: STM32MP25XXAJ I_Os (U10.E15), eMMC (R44.1 U24.A3)
eMMC.SDMMC2_D1: STM32MP25XXAJ I_Os (U10.A15), eMMC (U24.A4)
eMMC.SDMMC2_D2: STM32MP25XXAJ I_Os (U10.C14), eMMC (U24.A5)
eMMC.SDMMC2_D3: STM32MP25XXAJ I_Os (U10.D15), eMMC (U24.B2)
eMMC.SDMMC2_D4: STM32MP25XXAJ I_Os (U10.E14), eMMC (U24.B3)
eMMC.SDMMC2_D5: STM32MP25XXAJ I_Os (U10.B15), eMMC (U24.B4)
eMMC.SDMMC2_D6: STM32MP25XXAJ I_Os (U10.A14), eMMC (U24.B5)
eMMC.SDMMC2_D7: STM32MP25XXAJ I_Os (U10.B14), eMMC (U24.B6)
I2C7.SCL: STM32MP25XXAJ I_Os (R261.1 U10.B12), PMIC (U26.33)
I2C7.SDA: STM32MP25XXAJ I_Os (R260.1 U10.D12), PMIC (U26.34)
MP257_WAKEUP: STM32MP25XXAJ I_Os (U10.P5), PMIC (U26.32)
NRST: STM32MP25XXAJ I_Os (C33.2 U10.N1), PMIC (R81.1)
NRSTC1MS: STM32MP25XXAJ I_Os (R27.1 R272.1 U10.P2), PMIC (R59.1), eMMC (D5.2)
PMIC_WAKEUPn: STM32MP25XXAJ I_Os (U10.K5), PMIC (R46.1)
PWR_CPU_ON: STM32MP25XXAJ I_Os (R272.2 U10.N2), PMIC (R60.1)
PWR_ON: STM32MP25XXAJ I_Os (U10.P3), PMIC (R2.1)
